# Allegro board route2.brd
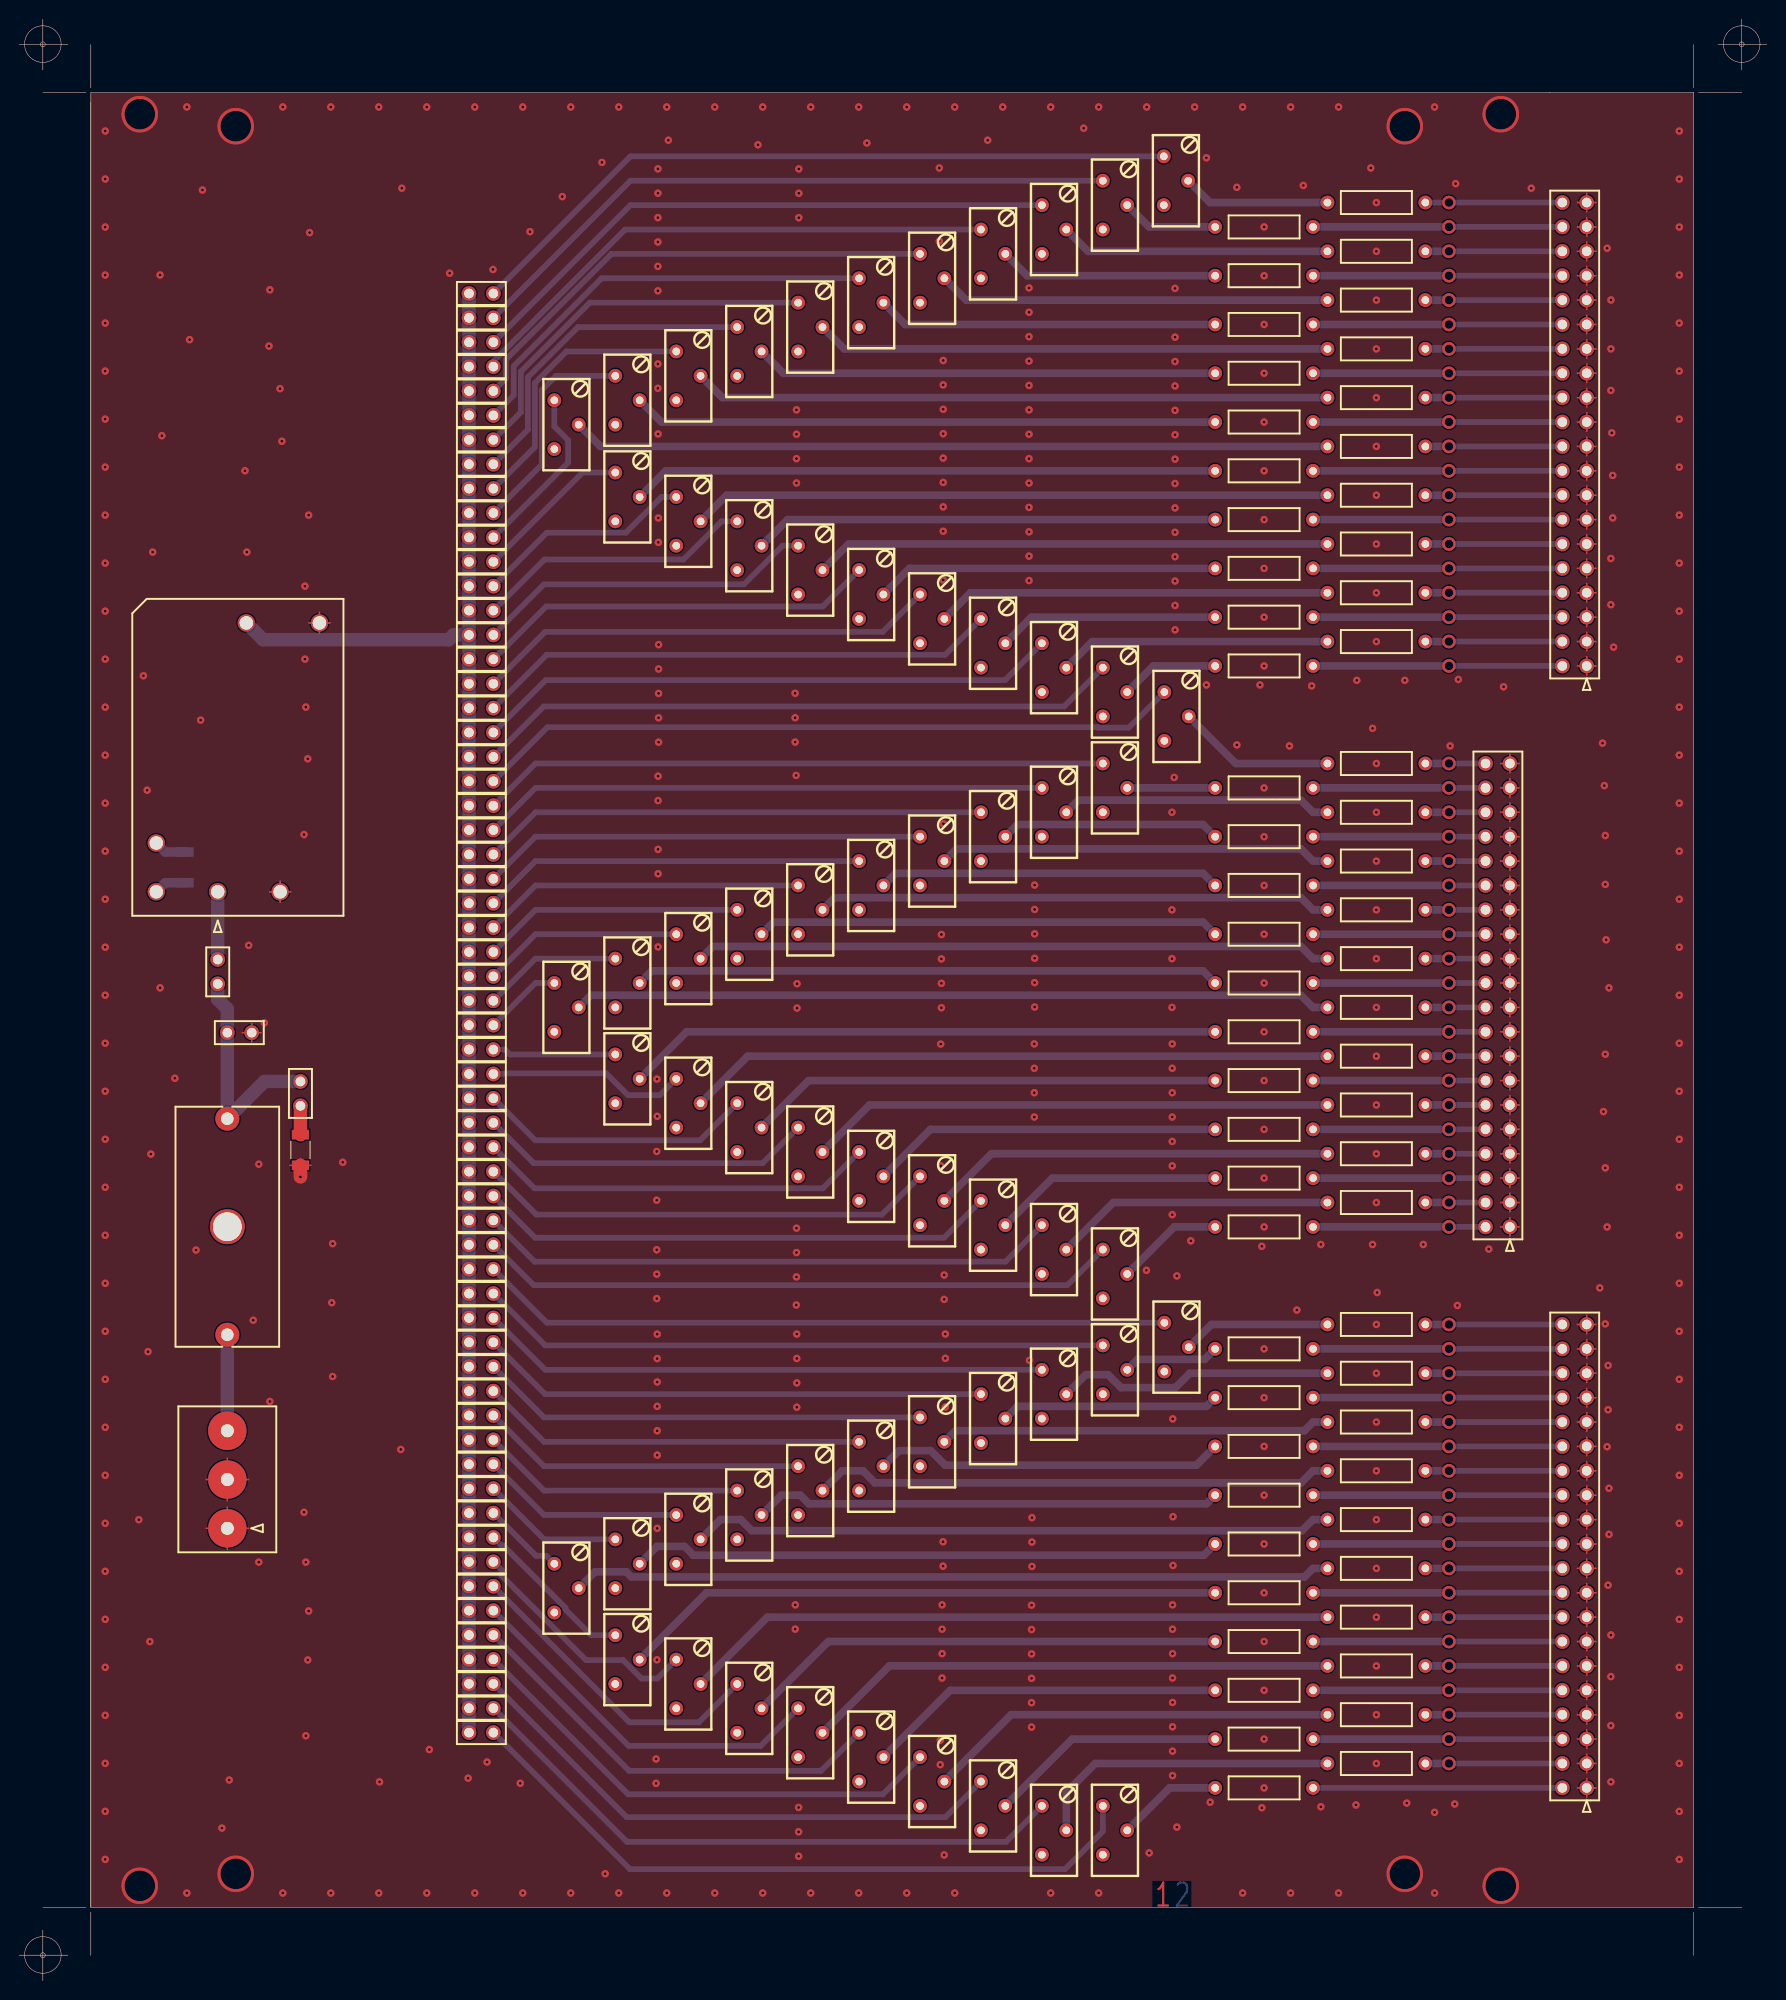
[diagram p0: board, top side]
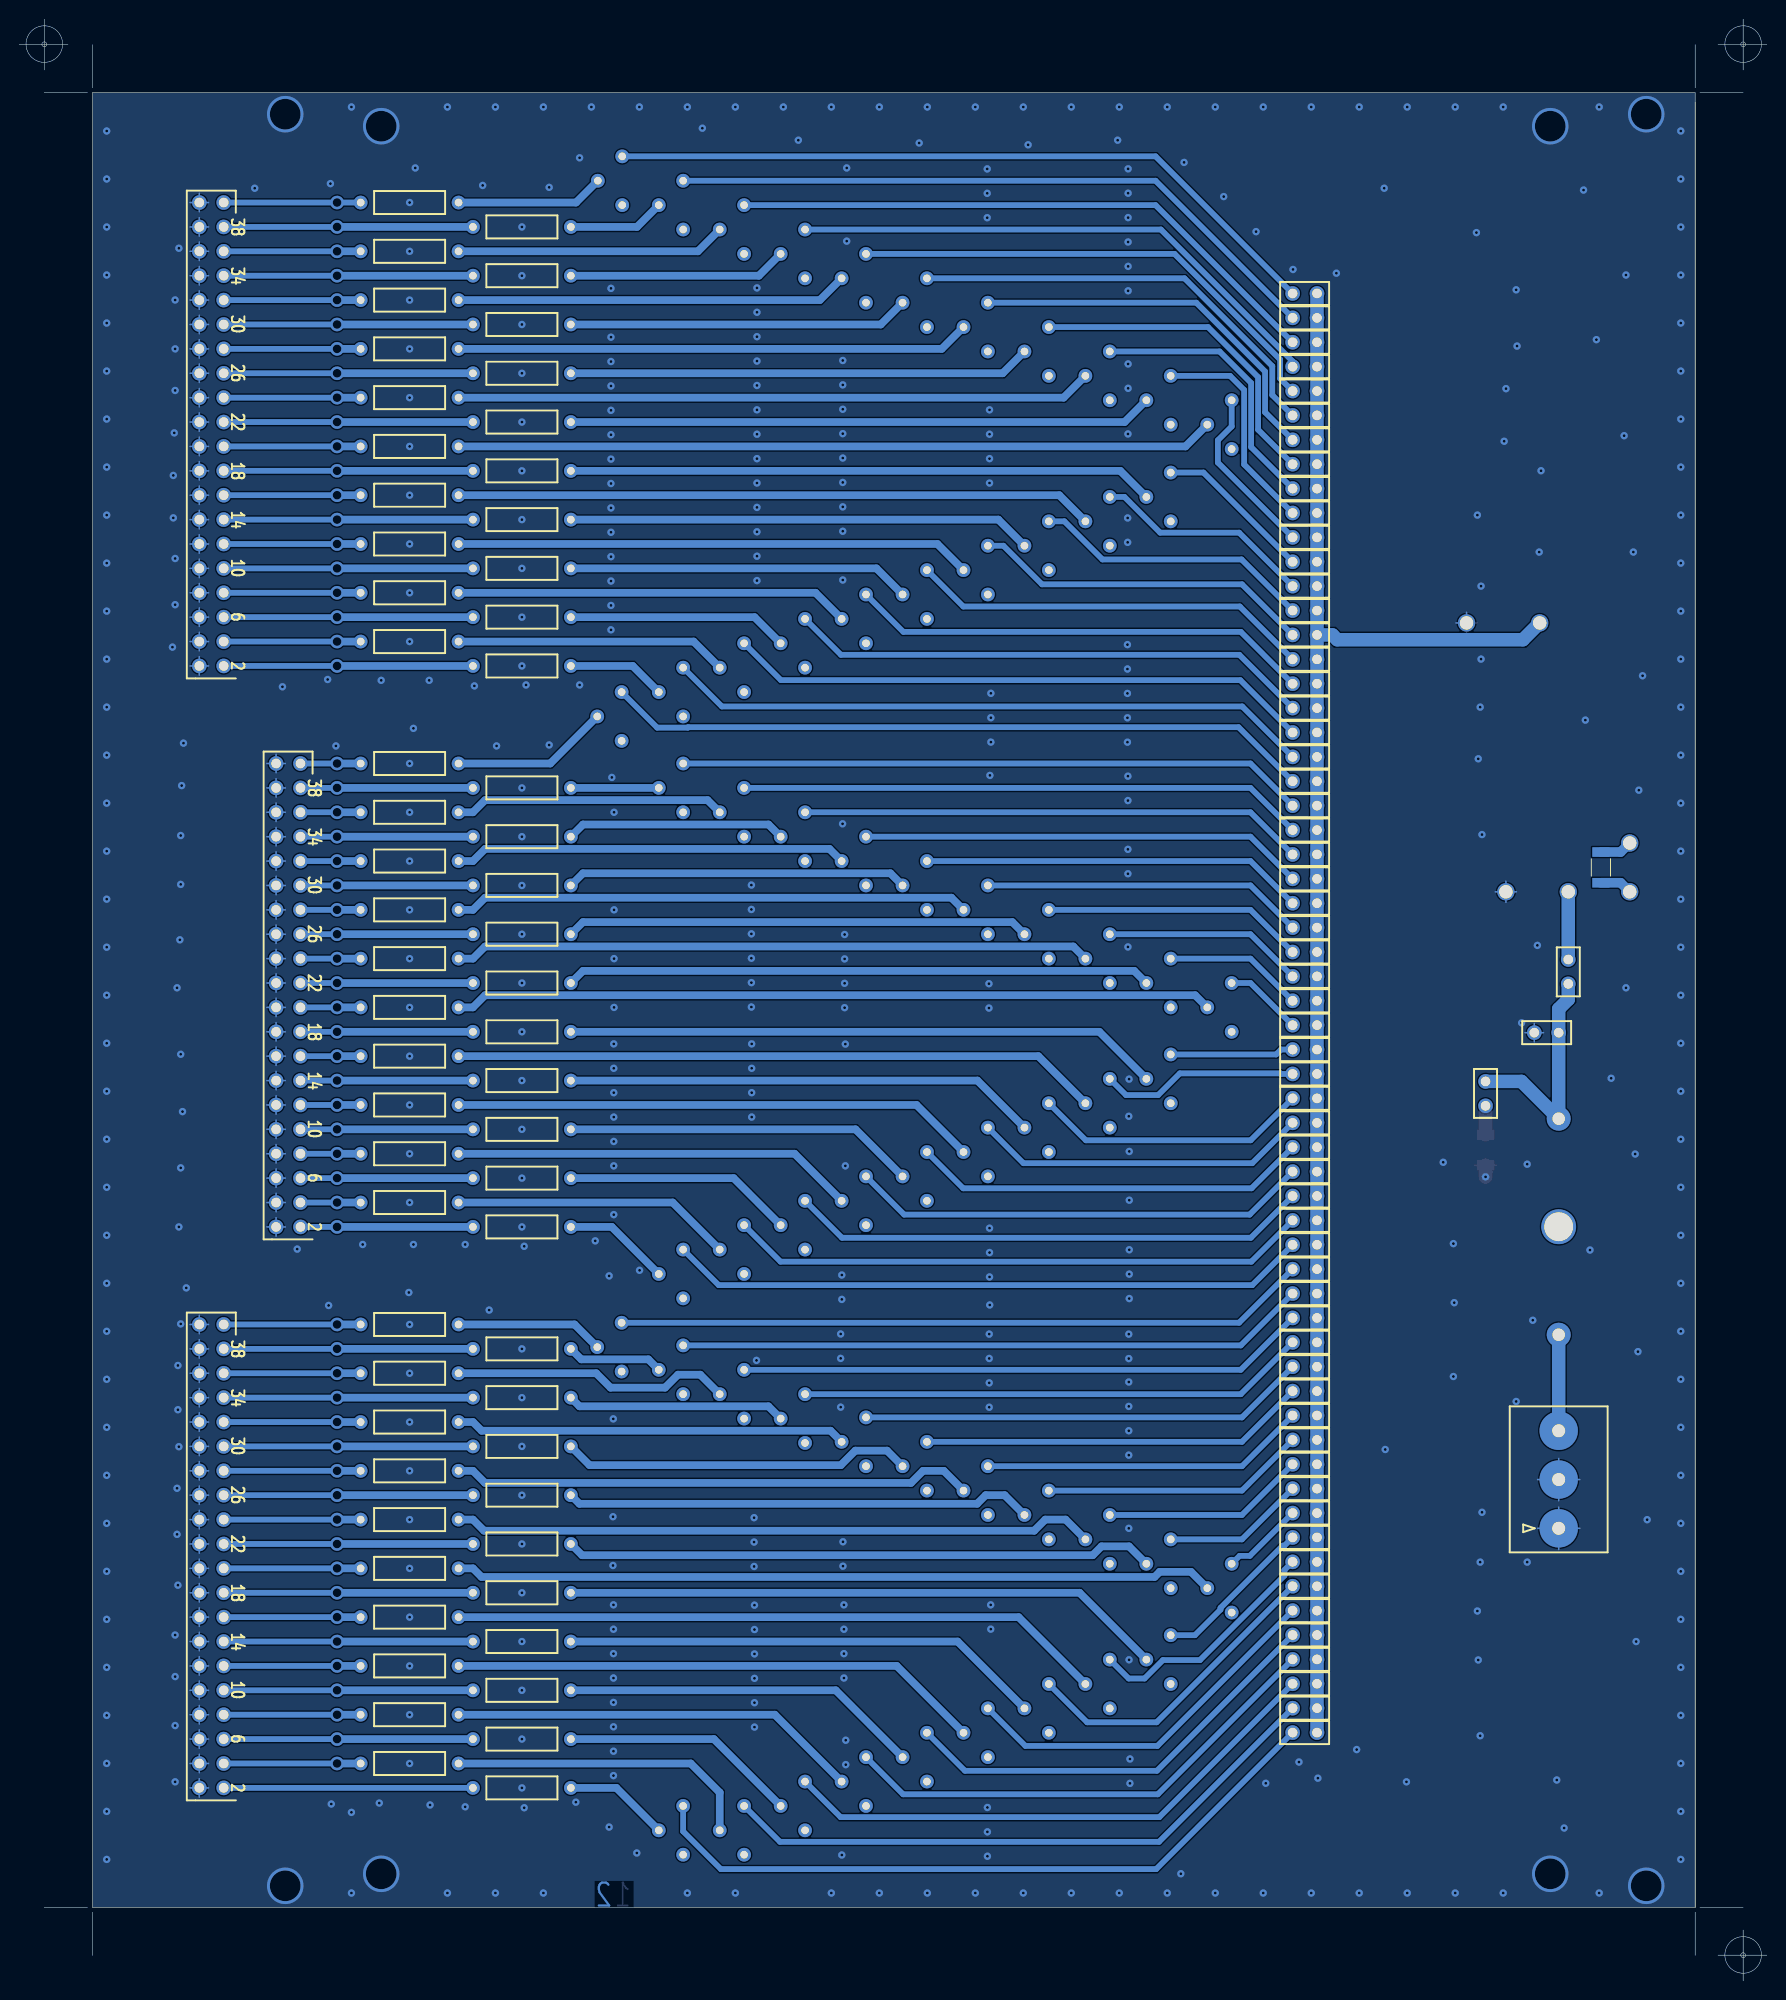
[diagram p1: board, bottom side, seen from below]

Outline 182.08 x 204.28 mm; copper layers: TOP, BOTTOM. Coordinates in mm from the lower left corner of the outline.
Outline path: 6.96,196.64 2.46,196.64 ; 6.96,7.64 2.46,7.64 ; 7.46,197.14 7.46,201.64 ; 7.46,7.64 7.46,196.64 174.46,196.64 174.46,7.64 7.46,7.64 ; 7.46,7.64 7.46,195.64 ; 7.46,7.14 7.46,2.64 ; 174.46,197.14 174.46,201.64 ; 174.46,7.14 174.46,2.64 ; 174.96,196.64 179.46,196.64 ; 174.96,7.64 179.46,7.64

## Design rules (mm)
constraint set DEFAULT: min track width 0.15, pair gap 0.15

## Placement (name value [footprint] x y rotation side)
B1  -  [BORNIER3B5080]  21.68 47.12 90 top
C1  47u  [S32X16_1206]  17.28 114.35 90 bottom
C2  100n  [S32X16_1206]  29.3 84.92 90 top
F1  10A  [FUSUP225X96]  21.68 67.28 90 top
J1  -  [CONHE13D2X20M]  163.31 136.93 0 top
J2  -  [CONHE13D2X20M]  155.31 78.51 0 top
J3  -  [CONHE13D2X20M]  163.31 20.09 0 top
NOREF  -  []  7.46 7.64 0 top
NOREF#2  -  []  2.46 2.64 0 top
NOREF#3  -  []  179.46 201.64 0 top
NOREF#4  -  []  2.46 201.64 0 top
NOREF#5  -  []  7.46 7.64 90 top
PO1  100  [POT_3296Y]  119.25 190 0 top
PO2  100  [POT_3296Y]  112.9 187.46 0 top
PO3  100  [POT_3296Y]  106.55 184.92 0 top
PO4  100  [POT_3296Y]  100.2 182.38 0 top
PO5  100  [POT_3296Y]  93.85 179.84 0 top
PO6  100  [POT_3296Y]  87.5 177.3 0 top
PO7  100  [POT_3296Y]  81.15 174.76 0 top
PO8  100  [POT_3296Y]  74.8 172.22 0 top
PO9  100  [POT_3296Y]  68.45 169.68 0 top
PO10  100  [POT_3296Y]  62.1 167.14 0 top
PO11  100  [POT_3296Y]  55.75 164.6 0 top
PO12  100  [POT_3296Y]  62.1 157.07 0 top
PO13  100  [POT_3296Y]  68.45 154.53 0 top
PO14  100  [POT_3296Y]  74.8 151.99 0 top
PO15  100  [POT_3296Y]  81.15 149.45 0 top
PO16  100  [POT_3296Y]  87.5 146.91 0 top
PO17  100  [POT_3296Y]  93.85 144.37 0 top
PO18  100  [POT_3296Y]  100.2 141.83 0 top
PO19  100  [POT_3296Y]  106.55 139.29 0 top
PO20  100  [POT_3296Y]  112.9 136.75 0 top
PO21  100  [POT_3296Y]  119.31 134.21 0 top
PO22  100  [POT_3296Y]  112.9 126.77 0 top
PO23  100  [POT_3296Y]  106.55 124.23 0 top
PO24  100  [POT_3296Y]  100.2 121.69 0 top
PO25  100  [POT_3296Y]  93.85 119.15 0 top
PO26  100  [POT_3296Y]  87.5 116.61 0 top
PO27  100  [POT_3296Y]  81.15 114.07 0 top
PO28  100  [POT_3296Y]  74.8 111.53 0 top
PO29  100  [POT_3296Y]  68.45 108.99 0 top
PO30  100  [POT_3296Y]  62.1 106.45 0 top
PO31  100  [POT_3296Y]  55.75 103.91 0 top
PO32  100  [POT_3296Y]  62.1 96.47 0 top
PO33  100  [POT_3296Y]  68.45 93.93 0 top
PO34  100  [POT_3296Y]  74.8 91.39 0 top
PO35  100  [POT_3296Y]  81.15 88.85 0 top
PO36  100  [POT_3296Y]  87.5 86.31 0 top
PO37  100  [POT_3296Y]  93.85 83.77 0 top
PO38  100  [POT_3296Y]  100.2 81.23 0 top
PO39  100  [POT_3296Y]  106.55 78.69 0 top
PO40  100  [POT_3296Y]  112.9 76.15 0 top
PO41  100  [POT_3296Y]  119.31 68.53 0 top
PO42  100  [POT_3296Y]  112.9 66.17 0 top
PO43  100  [POT_3296Y]  106.55 63.63 0 top
PO44  100  [POT_3296Y]  100.2 61.09 0 top
PO45  100  [POT_3296Y]  93.85 58.67 0 top
PO46  100  [POT_3296Y]  87.5 56.13 0 top
PO47  100  [POT_3296Y]  81.15 53.59 0 top
PO48  100  [POT_3296Y]  74.8 51.05 0 top
PO49  100  [POT_3296Y]  68.45 48.51 0 top
PO50  100  [POT_3296Y]  62.1 45.97 0 top
PO51  100  [POT_3296Y]  55.75 43.43 0 top
PO52  100  [POT_3296Y]  62.1 35.99 0 top
PO53  100  [POT_3296Y]  68.45 33.45 0 top
PO54  100  [POT_3296Y]  74.8 30.91 0 top
PO55  100  [POT_3296Y]  81.15 28.37 0 top
PO56  100  [POT_3296Y]  87.5 25.83 0 top
PO57  100  [POT_3296Y]  93.85 23.29 0 top
PO58  100  [POT_3296Y]  100.2 20.75 0 top
PO59  100  [POT_3296Y]  106.55 18.21 0 top
PO60  100  [POT_3296Y]  112.9 18.21 0 top
R1  100  [R100]  146.5 185.19 180 top
R2  100  [R100]  134.8 182.65 180 top
R3  100  [R100]  146.5 180.11 180 top
R4  100  [R100]  134.8 177.57 180 top
R5  100  [R100]  146.5 175.03 180 top
R6  100  [R100]  134.8 172.49 180 top
R7  100  [R100]  146.5 169.95 180 top
R8  100  [R100]  134.8 167.41 180 top
R9  100  [R100]  146.5 164.87 180 top
R10  100  [R100]  134.8 162.33 180 top
R11  100  [R100]  146.5 159.79 180 top
R12  100  [R100]  134.8 157.25 180 top
R13  100  [R100]  146.5 154.71 180 top
R14  100  [R100]  134.8 152.17 180 top
R15  100  [R100]  146.5 149.63 180 top
R16  100  [R100]  134.8 147.09 180 top
R17  100  [R100]  146.5 144.55 180 top
R18  100  [R100]  134.8 142.01 180 top
R19  100  [R100]  146.5 139.47 180 top
R20  100  [R100]  134.8 136.93 180 top
R21  100  [R100]  146.5 126.77 180 top
R22  100  [R100]  134.8 124.23 180 top
R23  100  [R100]  146.5 121.69 180 top
R24  100  [R100]  134.8 119.15 180 top
R25  100  [R100]  146.5 116.61 180 top
R26  100  [R100]  134.8 114.07 180 top
R27  100  [R100]  146.5 111.53 180 top
R28  100  [R100]  134.8 108.99 180 top
R29  100  [R100]  146.5 106.45 180 top
R30  100  [R100]  134.8 103.91 180 top
R31  100  [R100]  146.5 101.37 180 top
R32  100  [R100]  134.8 98.83 180 top
R33  100  [R100]  146.5 96.29 180 top
R34  100  [R100]  134.8 93.75 180 top
R35  100  [R100]  146.5 91.21 180 top
R36  100  [R100]  134.8 88.67 180 top
R37  100  [R100]  146.5 86.13 180 top
R38  100  [R100]  134.8 83.59 180 top
R39  100  [R100]  146.5 81.05 180 top
R40  100  [R100]  134.8 78.51 180 top
R41  100  [R100]  146.5 68.35 180 top
R42  100  [R100]  134.8 65.81 180 top
R43  100  [R100]  146.5 63.27 180 top
R44  100  [R100]  134.8 60.73 180 top
R45  100  [R100]  146.5 58.19 180 top
R46  100  [R100]  134.8 55.65 180 top
R47  100  [R100]  146.5 53.11 180 top
R48  100  [R100]  134.8 50.57 180 top
R49  100  [R100]  146.5 48.03 180 top
R50  100  [R100]  134.8 45.49 180 top
R51  100  [R100]  146.5 42.95 180 top
R52  100  [R100]  134.8 40.41 180 top
R53  100  [R100]  146.5 37.87 180 top
R54  100  [R100]  134.8 35.33 180 top
R55  100  [R100]  146.5 32.79 180 top
R56  100  [R100]  134.8 30.25 180 top
R57  100  [R100]  146.5 27.71 180 top
R58  100  [R100]  134.8 25.17 180 top
R59  100  [R100]  146.5 22.63 180 top
R60  100  [R100]  134.8 20.09 180 top
S1  -  [CONHE13D2M]  49.4 175.72 180 top
S2  -  [CONHE13D2M]  49.4 173.18 180 top
S3  -  [CONHE13D2M]  49.4 170.64 180 top
S4  -  [CONHE13D2M]  49.4 168.1 180 top
S5  -  [CONHE13D2M]  49.4 165.56 180 top
S6  -  [CONHE13D2M]  49.4 163.02 180 top
S7  -  [CONHE13D2M]  49.4 160.48 180 top
S8  -  [CONHE13D2M]  49.4 157.94 180 top
S9  -  [CONHE13D2M]  49.4 155.4 180 top
S10  -  [CONHE13D2M]  49.4 152.86 180 top
S11  -  [CONHE13D2M]  49.4 150.32 180 top
S12  -  [CONHE13D2M]  49.4 147.78 180 top
S13  -  [CONHE13D2M]  49.4 145.24 180 top
S14  -  [CONHE13D2M]  49.4 142.7 180 top
S15  -  [CONHE13D2M]  49.4 140.16 180 top
S16  -  [CONHE13D2M]  49.4 137.62 180 top
S17  -  [CONHE13D2M]  49.4 135.08 180 top
S18  -  [CONHE13D2M]  49.4 132.54 180 top
S19  -  [CONHE13D2M]  49.4 130 180 top
S20  -  [CONHE13D2M]  49.4 127.46 180 top
S21  -  [CONHE13D2M]  49.4 124.92 180 top
S22  -  [CONHE13D2M]  49.4 122.38 180 top
S23  -  [CONHE13D2M]  49.4 119.84 180 top
S24  -  [CONHE13D2M]  49.4 117.3 180 top
S25  -  [CONHE13D2M]  49.4 114.76 180 top
S26  -  [CONHE13D2M]  49.4 112.22 180 top
S27  -  [CONHE13D2M]  49.4 109.68 180 top
S28  -  [CONHE13D2M]  49.4 107.14 180 top
S29  -  [CONHE13D2M]  49.4 104.6 180 top
S30  -  [CONHE13D2M]  49.4 102.06 180 top
S31  -  [CONHE13D2M]  49.4 99.52 180 top
S32  -  [CONHE13D2M]  49.4 96.98 180 top
S33  -  [CONHE13D2M]  49.4 94.44 180 top
S34  -  [CONHE13D2M]  49.4 91.9 180 top
S35  -  [CONHE13D2M]  49.4 89.35 180 top
S36  -  [CONHE13D2M]  49.4 86.81 180 top
S37  -  [CONHE13D2M]  49.4 84.27 180 top
S38  -  [CONHE13D2M]  49.4 81.73 180 top
S39  -  [CONHE13D2M]  49.4 79.19 180 top
S40  -  [CONHE13D2M]  49.4 76.65 180 top
S41  -  [CONHE13D2M]  49.4 74.11 180 top
S42  -  [CONHE13D2M]  49.4 71.57 180 top
S43  -  [CONHE13D2M]  49.4 69.03 180 top
S44  -  [CONHE13D2M]  49.4 66.49 180 top
S45  -  [CONHE13D2M]  49.4 63.95 180 top
S46  -  [CONHE13D2M]  49.4 61.41 180 top
S47  -  [CONHE13D2M]  49.4 58.87 180 top
S48  -  [CONHE13D2M]  49.4 56.33 180 top
S49  -  [CONHE13D2M]  49.4 53.79 180 top
S50  -  [CONHE13D2M]  49.4 51.25 180 top
S51  -  [CONHE13D2M]  49.4 48.71 180 top
S52  -  [CONHE13D2M]  49.4 46.17 180 top
S53  -  [CONHE13D2M]  49.4 43.63 180 top
S54  -  [CONHE13D2M]  49.4 41.09 180 top
S55  -  [CONHE13D2M]  49.4 38.55 180 top
S56  -  [CONHE13D2M]  49.4 36.01 180 top
S57  -  [CONHE13D2M]  49.4 33.47 180 top
S58  -  [CONHE13D2M]  49.4 30.93 180 top
S59  -  [CONHE13D2M]  49.4 28.39 180 top
S60  -  [CONHE13D2M]  49.4 25.85 180 top
S61  -  [CONHE13D2M]  20.68 103.82 90 top
S62  -  [CONHE13D2M]  21.68 98.74 0 top
S63  -  [CONHE13D2M]  29.3 93.66 270 top
U1  -  [CONV_TUHS10]  20.68 113.41 90 top

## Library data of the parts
B1 = BORNIER3B: part number: BORNIER3B5080
C1 = CAPA: part number: CAPA-47U,C1206S6.3V20%
C2 = CAPA: part number: CAPA-100N,C1206S50V5%
F1 = FUSUP2P: part number: POLYFUSE-10A,W
J1-J3 = CON40P: part number: CON40P-HE13D
PO1-PO60 = POT: part number: POT-100,1/2W11T_D
R1-R60 = RGEN: part number: RGEN-100,M500MW5%
S1-S63 = STRAP: part number: STRAP-2X1
U1 = CONVAC_DC_TUHS10: part number: CONVAC_DC

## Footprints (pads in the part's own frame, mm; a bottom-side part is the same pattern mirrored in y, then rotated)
BORNIER3B5080
  round 4 hole 1.35: 1(0,0) 2(5.08,0) 3(10.16,0)
CONHE13D2M
  round 1.52 hole 1: 1(0,0) 2(2.54,0)
CONHE13D2X20M
  round 1.52 hole 1: 1(0,0) 2(-2.54,0) 3(0,2.54) 4(-2.54,2.54) 5(0,5.08) 6(-2.54,5.08) 7(0,7.62) 8(-2.54,7.62) 9(0,10.16) 10(-2.54,10.16) 11(0,12.7) 12(-2.54,12.7) 13(0,15.24) 14(-2.54,15.24) 15(0,17.78) 16(-2.54,17.78) 17(0,20.32) 18(-2.54,20.32) 19(0,22.86) 20(-2.54,22.86) 21(0,25.4) 22(-2.54,25.4) 23(0,27.94) 24(-2.54,27.94) 25(0,30.48) 26(-2.54,30.48) 27(0,33.02) 28(-2.54,33.02) 29(0,35.56) 30(-2.54,35.56) 31(0,38.1) 32(-2.54,38.1) 33(0,40.64) 34(-2.54,40.64) 35(0,43.18) 36(-2.54,43.18) 37(0,45.72) 38(-2.54,45.72) 39(0,48.26) 40(-2.54,48.26)
CONV_TUHS10
  round 1.8 hole 1.4: 1(0,0) 2(0,-6.5) 3(0,6.4) 4(5.08,6.4) 5(28,-2.98) 6(28,-10.6)
FUSUP225X96
  round 3.63 hole 3: (11.25,0)
  round 2.5 hole 1.3: 1(0,0) 2(22.5,0)
POT_3296Y
  round 1.43 hole 0.8: 1(0,0) 2(2.54,-2.54) 3(0,-5.08)
R100
  round 1.43 hole 0.8: 1(0,0) 2(10.2,0)
S32X16_1206
  rect 1x1.8 smd: 1(0,0) 2(3.2,0)

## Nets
GND: B1.1 B1.2 C2.1 J1.1 J1.3 J1.5 J1.7 J1.9 J1.11 J1.13 J1.15 J1.17 J1.19 J1.21 J1.23 J1.25 J1.27 J1.29 J1.31 J1.33 J1.35 J1.37 J1.39 J2.1 J2.3 J2.5 J2.7 J2.9 J2.11 J2.13 J2.15 J2.17 J2.19 J2.21 J2.23 J2.25 J2.27 J2.29 J2.31 J2.33 J2.35 J2.37 J2.39 J3.1 J3.3 J3.5 J3.7 J3.9 J3.11 J3.13 J3.15 J3.17 J3.19 J3.21 J3.23 J3.25 J3.27 J3.29 J3.31 J3.33 J3.35 J3.37 J3.39 S62.2(B) U1.2(AC2) U1.6
UNNAMED_1_BORNIER3B_I185_C: B1.3(C) F1.1
UNNAMED_1_CAPA_I190_B: C2.2(B<0>) S63.2(B)
UNNAMED_1_CAPA_I193_A: C1.1 U1.3
UNNAMED_1_CAPA_I193_B: C1.2(B<0>) U1.4
UNNAMED_1_CON40P_I1_A: J1.10(A<9>) R16.1
UNNAMED_1_CON40P_I1_A_1: J1.8 R17.1
UNNAMED_1_CON40P_I1_A_2: J1.6 R18.1
UNNAMED_1_CON40P_I1_A_3: J1.4 R19.1
UNNAMED_1_CON40P_I1_A_4: J1.40 R1.1
UNNAMED_1_CON40P_I1_A_5: J1.38 R2.1
UNNAMED_1_CON40P_I1_A_6: J1.36 R3.1
UNNAMED_1_CON40P_I1_A_7: J1.34 R4.1
UNNAMED_1_CON40P_I1_A_8: J1.32 R5.1
UNNAMED_1_CON40P_I1_A_9: J1.30 R6.1
UNNAMED_1_CON40P_I1_A_10: J1.28 R7.1
UNNAMED_1_CON40P_I1_A_11: J1.26 R8.1
UNNAMED_1_CON40P_I1_A_12: J1.24 R9.1
UNNAMED_1_CON40P_I1_A_13: J1.22 R10.1
UNNAMED_1_CON40P_I1_A_14: J1.2 R20.1
UNNAMED_1_CON40P_I1_A_15: J1.20 R11.1
UNNAMED_1_CON40P_I1_A_16: J1.18 R12.1
UNNAMED_1_CON40P_I1_A_17: J1.16 R13.1
UNNAMED_1_CON40P_I1_A_18: J1.14 R14.1
UNNAMED_1_CON40P_I1_A_19: J1.12 R15.1
UNNAMED_1_CON40P_I2_A: J3.28 R47.1
UNNAMED_1_CON40P_I2_A_1: J3.30 R46.1
UNNAMED_1_CON40P_I2_A_2: J3.38 R42.1
UNNAMED_1_CON40P_I2_A_3: J3.32 R45.1
UNNAMED_1_CON40P_I2_A_4: J3.34 R44.1
UNNAMED_1_CON40P_I2_A_5: J3.36 R43.1
UNNAMED_1_CON40P_I2_A_6: J3.40 R41.1
UNNAMED_1_CON40P_I2_A_7: J3.6 R58.1
UNNAMED_1_CON40P_I2_A_8: J3.8 R57.1
UNNAMED_1_CON40P_I2_A_9: J3.4 R59.1
UNNAMED_1_CON40P_I2_A_10: J3.2 R60.1
UNNAMED_1_CON40P_I2_A_11: J3.10(A<9>) R56.1
UNNAMED_1_CON40P_I2_A_12: J3.12 R55.1
UNNAMED_1_CON40P_I2_A_13: J3.14 R54.1
UNNAMED_1_CON40P_I2_A_14: J3.16 R53.1
UNNAMED_1_CON40P_I2_A_15: J3.18 R52.1
UNNAMED_1_CON40P_I2_A_16: J3.20 R51.1
UNNAMED_1_CON40P_I2_A_17: J3.22 R50.1
UNNAMED_1_CON40P_I2_A_18: J3.24 R49.1
UNNAMED_1_CON40P_I2_A_19: J3.26 R48.1
UNNAMED_1_CON40P_I3_A: J2.28 R27.1
UNNAMED_1_CON40P_I3_A_1: J2.30 R26.1
UNNAMED_1_CON40P_I3_A_2: J2.38 R22.1
UNNAMED_1_CON40P_I3_A_3: J2.32 R25.1
UNNAMED_1_CON40P_I3_A_4: J2.34 R24.1
UNNAMED_1_CON40P_I3_A_5: J2.36 R23.1
UNNAMED_1_CON40P_I3_A_6: J2.40 R21.1
UNNAMED_1_CON40P_I3_A_7: J2.6 R38.1
UNNAMED_1_CON40P_I3_A_8: J2.8 R37.1
UNNAMED_1_CON40P_I3_A_9: J2.4 R39.1
UNNAMED_1_CON40P_I3_A_10: J2.2 R40.1
UNNAMED_1_CON40P_I3_A_11: J2.10(A<9>) R36.1
UNNAMED_1_CON40P_I3_A_12: J2.12 R35.1
UNNAMED_1_CON40P_I3_A_13: J2.14 R34.1
UNNAMED_1_CON40P_I3_A_14: J2.16 R33.1
UNNAMED_1_CON40P_I3_A_15: J2.18 R32.1
UNNAMED_1_CON40P_I3_A_16: J2.20 R31.1
UNNAMED_1_CON40P_I3_A_17: J2.22 R30.1
UNNAMED_1_CON40P_I3_A_18: J2.24 R29.1
UNNAMED_1_CON40P_I3_A_19: J2.26 R28.1
UNNAMED_1_CONVACDCTUHS10_I194_A: S61.2(B) U1.1
UNNAMED_1_FUSUP2P_I186_B: F1.2(B) S61.1 S62.1 S63.1
UNNAMED_1_POT_I5_A: PO1.1 S1.1
UNNAMED_1_POT_I5_B: PO1.2 R1.2(B<0>)
UNNAMED_1_POT_I7_A: PO2.1 S2.1
UNNAMED_1_POT_I7_B: PO2.2 R2.2(B<0>)
UNNAMED_1_POT_I26_A: PO3.1 S3.1
UNNAMED_1_POT_I26_B: PO3.2 R3.2(B<0>)
UNNAMED_1_POT_I27_A: PO4.1 S4.1
UNNAMED_1_POT_I27_B: PO4.2 R4.2(B<0>)
UNNAMED_1_POT_I28_A: PO5.1 S5.1
UNNAMED_1_POT_I28_B: PO5.2 R5.2(B<0>)
UNNAMED_1_POT_I29_A: PO6.1 S6.1
UNNAMED_1_POT_I29_B: PO6.2 R6.2(B<0>)
UNNAMED_1_POT_I30_A: PO7.1 S7.1
UNNAMED_1_POT_I30_B: PO7.2 R7.2(B<0>)
UNNAMED_1_POT_I31_A: PO8.1 S8.1
UNNAMED_1_POT_I31_B: PO8.2 R8.2(B<0>)
UNNAMED_1_POT_I32_A: PO9.1 S9.1
UNNAMED_1_POT_I32_B: PO9.2 R9.2(B<0>)
UNNAMED_1_POT_I33_A: PO10.1 S10.1
UNNAMED_1_POT_I33_B: PO10.2 R10.2(B<0>)
UNNAMED_1_POT_I34_A: PO11.1 S11.1
UNNAMED_1_POT_I34_B: PO11.2 R11.2(B<0>)
UNNAMED_1_POT_I35_A: PO12.1 S12.1
UNNAMED_1_POT_I35_B: PO12.2 R12.2(B<0>)
UNNAMED_1_POT_I36_A: PO13.1 S13.1
UNNAMED_1_POT_I36_B: PO13.2 R13.2(B<0>)
UNNAMED_1_POT_I37_A: PO14.1 S14.1
UNNAMED_1_POT_I37_B: PO14.2 R14.2(B<0>)
UNNAMED_1_POT_I38_A: PO15.1 S15.1
UNNAMED_1_POT_I38_B: PO15.2 R15.2(B<0>)
UNNAMED_1_POT_I39_A: PO16.1 S16.1
UNNAMED_1_POT_I39_B: PO16.2 R16.2(B<0>)
UNNAMED_1_POT_I40_A: PO17.1 S17.1
UNNAMED_1_POT_I40_B: PO17.2 R17.2(B<0>)
UNNAMED_1_POT_I41_A: PO18.1 S18.1
UNNAMED_1_POT_I41_B: PO18.2 R18.2(B<0>)
UNNAMED_1_POT_I42_A: PO19.1 S19.1
UNNAMED_1_POT_I42_B: PO19.2 R19.2(B<0>)
UNNAMED_1_POT_I43_A: PO20.1 S20.1
UNNAMED_1_POT_I43_B: PO20.2 R20.2(B<0>)
UNNAMED_1_POT_I44_A: PO40.1 S40.1
UNNAMED_1_POT_I44_B: PO40.2 R40.2(B<0>)
UNNAMED_1_POT_I45_A: PO39.1 S39.1
UNNAMED_1_POT_I45_B: PO39.2 R39.2(B<0>)
UNNAMED_1_POT_I46_A: PO38.1 S38.1
UNNAMED_1_POT_I46_B: PO38.2 R38.2(B<0>)
UNNAMED_1_POT_I47_A: PO33.1 S33.1
UNNAMED_1_POT_I47_B: PO33.2 R33.2(B<0>)
UNNAMED_1_POT_I48_A: PO32.1 S32.1
UNNAMED_1_POT_I48_B: PO32.2 R32.2(B<0>)
UNNAMED_1_POT_I49_A: PO31.1 S31.1
UNNAMED_1_POT_I49_B: PO31.2 R31.2(B<0>)
UNNAMED_1_POT_I50_A: PO30.1 S30.1
UNNAMED_1_POT_I50_B: PO30.2 R30.2(B<0>)
UNNAMED_1_POT_I51_A: PO29.1 S29.1
UNNAMED_1_POT_I51_B: PO29.2 R29.2(B<0>)
UNNAMED_1_POT_I52_A: PO27.1 S27.1
UNNAMED_1_POT_I52_B: PO27.2 R27.2(B<0>)
UNNAMED_1_POT_I53_A: PO28.1 S28.1
UNNAMED_1_POT_I53_B: PO28.2 R28.2(B<0>)
UNNAMED_1_POT_I54_A: PO26.1 S26.1
UNNAMED_1_POT_I54_B: PO26.2 R26.2(B<0>)
UNNAMED_1_POT_I55_A: PO25.1 S25.1
UNNAMED_1_POT_I55_B: PO25.2 R25.2(B<0>)
UNNAMED_1_POT_I56_A: PO24.1 S24.1
UNNAMED_1_POT_I56_B: PO24.2 R24.2(B<0>)
UNNAMED_1_POT_I57_A: PO22.1 S22.1
UNNAMED_1_POT_I57_B: PO22.2 R22.2(B<0>)
UNNAMED_1_POT_I58_A: PO21.1 S21.1
UNNAMED_1_POT_I58_B: PO21.2 R21.2(B<0>)
UNNAMED_1_POT_I59_A: PO23.1 S23.1
UNNAMED_1_POT_I59_B: PO23.2 R23.2(B<0>)
UNNAMED_1_POT_I72_A: PO37.1 S37.1
UNNAMED_1_POT_I72_B: PO37.2 R37.2(B<0>)
UNNAMED_1_POT_I73_A: PO36.1 S36.1
UNNAMED_1_POT_I73_B: PO36.2 R36.2(B<0>)
UNNAMED_1_POT_I74_A: PO35.1 S35.1
UNNAMED_1_POT_I74_B: PO35.2 R35.2(B<0>)
UNNAMED_1_POT_I75_A: PO34.1 S34.1
UNNAMED_1_POT_I75_B: PO34.2 R34.2(B<0>)
UNNAMED_1_POT_I84_A: PO60.1 S60.1
UNNAMED_1_POT_I84_B: PO60.2 R60.2(B<0>)
UNNAMED_1_POT_I85_A: PO59.1 S59.1
UNNAMED_1_POT_I85_B: PO59.2 R59.2(B<0>)
UNNAMED_1_POT_I86_A: PO58.1 S58.1
UNNAMED_1_POT_I86_B: PO58.2 R58.2(B<0>)
UNNAMED_1_POT_I87_A: PO53.1 S53.1
UNNAMED_1_POT_I87_B: PO53.2 R53.2(B<0>)
UNNAMED_1_POT_I88_A: PO52.1 S52.1
UNNAMED_1_POT_I88_B: PO52.2 R52.2(B<0>)
UNNAMED_1_POT_I89_A: PO51.1 S51.1
UNNAMED_1_POT_I89_B: PO51.2 R51.2(B<0>)
UNNAMED_1_POT_I90_A: PO50.1 S50.1
UNNAMED_1_POT_I90_B: PO50.2 R50.2(B<0>)
UNNAMED_1_POT_I91_A: PO49.1 S49.1
UNNAMED_1_POT_I91_B: PO49.2 R49.2(B<0>)
UNNAMED_1_POT_I92_A: PO47.1 S47.1
UNNAMED_1_POT_I92_B: PO47.2 R47.2(B<0>)
UNNAMED_1_POT_I93_A: PO48.1 S48.1
UNNAMED_1_POT_I93_B: PO48.2 R48.2(B<0>)
UNNAMED_1_POT_I94_A: PO46.1 S46.1
UNNAMED_1_POT_I94_B: PO46.2 R46.2(B<0>)
UNNAMED_1_POT_I95_A: PO45.1 S45.1
UNNAMED_1_POT_I95_B: PO45.2 R45.2(B<0>)
UNNAMED_1_POT_I96_A: PO44.1 S44.1
UNNAMED_1_POT_I96_B: PO44.2 R44.2(B<0>)
UNNAMED_1_POT_I97_A: PO42.1 S42.1
UNNAMED_1_POT_I97_B: PO42.2 R42.2(B<0>)
UNNAMED_1_POT_I98_A: PO41.1 S41.1
UNNAMED_1_POT_I98_B: PO41.2 R41.2(B<0>)
UNNAMED_1_POT_I99_A: PO43.1 S43.1
UNNAMED_1_POT_I99_B: PO43.2 R43.2(B<0>)
UNNAMED_1_POT_I112_A: PO57.1 S57.1
UNNAMED_1_POT_I112_B: PO57.2 R57.2(B<0>)
UNNAMED_1_POT_I113_A: PO56.1 S56.1
UNNAMED_1_POT_I113_B: PO56.2 R56.2(B<0>)
UNNAMED_1_POT_I114_A: PO55.1 S55.1
UNNAMED_1_POT_I114_B: PO55.2 R55.2(B<0>)
UNNAMED_1_POT_I115_A: PO54.1 S54.1
UNNAMED_1_POT_I115_B: PO54.2 R54.2(B<0>)
UNNAMED_1_STRAP_I125_B: S1.2(B) S2.2(B) S3.2(B) S4.2(B) S5.2(B) S6.2(B) S7.2(B) S8.2(B) S9.2(B) S10.2(B) S11.2(B) S12.2(B) S13.2(B) S14.2(B) S15.2(B) S16.2(B) S17.2(B) S18.2(B) S19.2(B) S20.2(B) S21.2(B) S22.2(B) S23.2(B) S24.2(B) S25.2(B) S26.2(B) S27.2(B) S28.2(B) S29.2(B) S30.2(B) S31.2(B) S32.2(B) S33.2(B) S34.2(B) S35.2(B) S36.2(B) S37.2(B) S38.2(B) S39.2(B) S40.2(B) S41.2(B) S42.2(B) S43.2(B) S44.2(B) S45.2(B) S46.2(B) S47.2(B) S48.2(B) S49.2(B) S50.2(B) S51.2(B) S52.2(B) S53.2(B) S54.2(B) S55.2(B) S56.2(B) S57.2(B) S58.2(B) S59.2(B) S60.2(B) U1.5

Pads without a net: PO1 3; PO2 3; PO3 3; PO4 3; PO5 3; PO6 3; PO7 3; PO8 3; PO9 3; PO10 3; PO11 3; PO12 3; PO13 3; PO14 3; PO15 3; PO16 3; PO17 3; PO18 3; PO19 3; PO20 3; PO21 3; PO22 3; PO23 3; PO24 3; PO25 3; PO26 3; PO27 3; PO28 3; PO29 3; PO30 3; PO31 3; PO32 3; PO33 3; PO34 3; PO35 3; PO36 3; PO37 3; PO38 3; PO39 3; PO40 3; PO41 3; PO42 3; PO43 3; PO44 3; PO45 3; PO46 3; PO47 3; PO48 3; PO49 3; PO50 3; PO51 3; PO52 3; PO53 3; PO54 3; PO55 3; PO56 3; PO57 3; PO58 3; PO59 3; PO60 3

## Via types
v1: diameter 1.42, hole 0.9, TOP to BOTTOM, 59 vias
v2: diameter 0.77, hole 0.3, TOP to BOTTOM, 480 vias
v3: diameter 3.8, hole 3.2, TOP to BOTTOM, 8 vias

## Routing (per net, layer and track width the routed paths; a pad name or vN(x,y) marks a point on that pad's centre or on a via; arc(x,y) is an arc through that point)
GND: length 524.3
  TOP w0.15: 163.31,143.59 J1.7 ; J1.7 164.27,144.55 ; J1.7 162.35,144.55 ; J1.7 163.31,145.51 ; J3.11 164.27,32.79 ; J3.11 162.35,32.79 ; J3.11 163.31,33.75 ; J3.11 163.31,31.83 ; 26.08,113.41 U1.2 ; U1.2 27.18,112.31 ; U1.2 28.28,113.41 ; U1.2 27.18,114.51 ; 162.35,167.41 J1.25 ; J1.25 163.31,168.37 ; J1.25 164.27,167.41 ; J1.25 163.31,166.45 ; J3.37 163.31,66.77 ; J3.37 163.31,64.85 ; J3.37 162.35,65.81 ; J3.37 164.27,65.81 ; 155.31,92.79 J2.13 ; J2.13 156.27,93.75 ; J2.13 155.31,94.71 ; J2.13 154.35,93.75 ; J1.39 164.27,185.19 ; J1.39 162.35,185.19 ; J1.39 163.31,184.23 ; J1.39 163.31,186.15 ; J2.21 155.31,104.87 ; J2.21 156.27,103.91 ; J2.21 154.35,103.91 ; J2.21 155.31,102.95 ; J3.21 163.31,46.45 ; J3.21 162.35,45.49 ; J3.21 164.27,45.49 ; J3.21 163.31,44.53 ; 31.28,140.31 U1.6 ; U1.6 31.28,142.51 ; U1.6 32.38,141.41 ; U1.6 30.18,141.41 ; 23.26,98.74 S62.2 ; S62.2 25.18,98.74 ; S62.2 24.22,99.7 ; S62.2 24.22,97.78 ; J1.3 163.31,140.43 ; J1.3 162.35,139.47 ; J1.3 163.31,138.51 ; J1.3 164.27,139.47 ; 162.35,30.25 J3.9 ; J3.9 164.27,30.25 ; J3.9 163.31,31.21 ; J3.9 163.31,29.29 ; 162.35,40.41 J3.17 ; J3.17 163.31,39.45 ; J3.17 163.31,41.37 ; J3.17 164.27,40.41 ; 162.35,149.63 J1.11 ; J1.11 163.31,148.67 ; J1.11 163.31,150.59 ; J1.11 164.27,149.63 ; J3.13 164.27,35.33 ; J3.13 162.35,35.33 ; J3.13 163.31,34.37 ; J3.13 163.31,36.29 ; 162.35,182.65 J1.37 ; J1.37 163.31,181.69 ; J1.37 163.31,183.61 ; J1.37 164.27,182.65 ; 154.35,81.05 J2.3 ; J2.3 155.31,82.01 ; J2.3 156.27,81.05 ; J2.3 155.31,80.09 ; J1.29 163.31,173.45 ; J1.29 164.27,172.49 ; J1.29 163.31,171.53 ; J1.29 162.35,172.49 ; 163.31,24.21 J3.5 ; J3.5 163.31,26.13 ; J3.5 164.27,25.17 ; J3.5 162.35,25.17 ; J2.11 156.27,91.21 ; J2.11 155.31,90.25 ; J2.11 154.35,91.21 ; J2.11 155.31,92.17 ; J3.1 163.31,21.05 ; J3.1 163.31,19.13 ; J3.1 162.35,20.09 ; J3.1 164.27,20.09 ; J2.31 156.27,116.61 ; J2.31 155.31,117.57 ; J2.31 154.35,116.61 ; J2.31 155.31,115.65 ; J2.37 156.27,124.23 ; J2.37 155.31,123.27 ; J2.37 154.35,124.23 ; J2.37 155.31,125.19 ; J2.5 156.27,83.59 ; J2.5 154.35,83.59 ; J2.5 155.31,84.55 ; J2.5 155.31,82.63 ; J3.15 163.31,38.83 ; J3.15 164.27,37.87 ; J3.15 163.31,36.91 ; J3.15 162.35,37.87 ; 162.35,169.95 J1.27 ; J1.27 163.31,168.99 ; J1.27 164.27,169.95 ; J1.27 163.31,170.91 ; 163.31,49.61 J3.25 ; J3.25 164.27,50.57 ; J3.25 162.35,50.57 ; J3.25 163.31,51.53 ; J3.19 163.31,43.91 ; J3.19 163.31,41.99 ; J3.19 164.27,42.95 ; J3.19 162.35,42.95 ; J3.39 164.27,68.35 ; J3.39 163.31,67.39 ; J3.39 162.35,68.35 ; J3.39 163.31,69.31 ; J1.9 164.27,147.09 ; J1.9 163.31,148.05 ; J1.9 163.31,146.13 ; J1.9 162.35,147.09 ; 155.31,120.73 J2.35 ; J2.35 155.31,122.65 ; J2.35 154.35,121.69 ; J2.35 156.27,121.69 ; B1.1 21.68,49.32 ; B1.1 23.88,47.12 ; B1.1 21.68,44.92 ; B1.1 19.48,47.12 ; 19.48,52.2 B1.2 ; B1.2 23.88,52.2 ; B1.2 21.68,50 ; B1.2 21.68,54.4 ; 162.35,27.71 J3.7 ; J3.7 163.31,26.75 ; J3.7 163.31,28.67 ; J3.7 164.27,27.71 ; 155.31,87.71 J2.9 ; J2.9 155.31,89.63 ; J2.9 154.35,88.67 ; J2.9 156.27,88.67 ; J1.35 164.27,180.11 ; J1.35 163.31,181.07 ; J1.35 163.31,179.15 ; J1.35 162.35,180.11 ; 162.35,142.01 J1.5 ; J1.5 163.31,142.97 ; J1.5 163.31,141.05 ; J1.5 164.27,142.01 ; J3.31 164.27,58.19 ; J3.31 162.35,58.19 ; J3.31 163.31,59.15 ; J3.31 163.31,57.23 ; 163.31,174.07 J1.31 ; J1.31 163.31,175.99 ; J1.31 162.35,175.03 ; J1.31 164.27,175.03 ; J1.17 164.27,157.25 ; J1.17 162.35,157.25 ; J1.17 163.31,158.21 ; J1.17 163.31,156.29 ; 163.31,47.07 J3.23 ; J3.23 164.27,48.03 ; J3.23 163.31,48.99 ; J3.23 162.35,48.03 ; J2.25 155.31,109.95 ; J2.25 155.31,108.03 ; J2.25 154.35,108.99 ; J2.25 156.27,108.99 ; 162.35,63.27 J3.35 ; J3.35 163.31,62.31 ; J3.35 164.27,63.27 ; J3.35 163.31,64.23 ; J2.17 156.27,98.83 ; J2.17 154.35,98.83 ; J2.17 155.31,97.87 ; J2.17 155.31,99.79 ; J1.13 164.27,152.17 ; J1.13 162.35,152.17 ; J1.13 163.31,151.21 ; J1.13 163.31,153.13 ; 163.31,153.75 J1.15 ; J1.15 163.31,155.67 ; J1.15 164.27,154.71 ; J1.15 162.35,154.71 ; J3.29 164.27,55.65 ; J3.29 163.31,56.61 ; J3.29 163.31,54.69 ; J3.29 162.35,55.65 ; C2.1 30.4,84.92 ; C2.1 29.3,85.62 ; C2.1 28.2,84.92 ; 162.35,162.33 J1.21 ; J1.21 163.31,161.37 ; J1.21 164.27,162.33 ; J1.21 163.31,163.29 ; J2.19 156.27,101.37 ; J2.19 155.31,100.41 ; J2.19 154.35,101.37 ; J2.19 155.31,102.33 ; 163.31,21.67 J3.3 ; J3.3 163.31,23.59 ; J3.3 164.27,22.63 ; J3.3 162.35,22.63 ; 162.35,60.73 J3.33 ; J3.33 163.31,59.77 ; J3.33 163.31,61.69 ; J3.33 164.27,60.73 ; J2.39 156.27,126.77 ; J2.39 155.31,127.73 ; J2.39 154.35,126.77 ; J2.39 155.31,125.81 ; 162.35,159.79 J1.19 ; J1.19 163.31,160.75 ; J1.19 164.27,159.79 ; J1.19 163.31,158.83 ; J1.33 163.31,178.53 ; J1.33 162.35,177.57 ; J1.33 164.27,177.57 ; J1.33 163.31,176.61 ; 163.31,52.15 J3.27 ; J3.27 163.31,54.07 ; J3.27 164.27,53.11 ; J3.27 162.35,53.11 ; J2.15 155.31,97.25 ; J2.15 156.27,96.29 ; J2.15 154.35,96.29 ; J2.15 155.31,95.33 ; 155.31,77.55 J2.1 ; J2.1 155.31,79.47 ; J2.1 156.27,78.51 ; J2.1 154.35,78.51 ; 154.35,106.45 J2.23 ; J2.23 156.27,106.45 ; J2.23 155.31,107.41 ; J2.23 155.31,105.49 ; 155.31,118.19 J2.33 ; J2.33 156.27,119.15 ; J2.33 155.31,120.11 ; J2.33 154.35,119.15 ; 163.31,135.97 J1.1 ; J1.1 163.31,137.89 ; J1.1 162.35,136.93 ; J1.1 164.27,136.93 ; 163.31,163.91 J1.23 ; J1.23 164.27,164.87 ; J1.23 163.31,165.83 ; J1.23 162.35,164.87 ; J2.27 155.31,112.49 ; J2.27 154.35,111.53 ; J2.27 156.27,111.53 ; J2.27 155.31,110.57 ; J2.7 155.31,87.09 ; J2.7 156.27,86.13 ; J2.7 155.31,85.17 ; J2.7 154.35,86.13 ; 154.35,114.07 J2.29 ; J2.29 155.31,113.11 ; J2.29 156.27,114.07 ; J2.29 155.31,115.03
  TOP w1.4: C2.1 v2(29.3,83.72)
  BOTTOM w0.15: U1.6 31.28,142.51 ; U1.6 30.66,141.41 ; U1.6 32.38,141.41 ; J1.25 164.27,167.41 ; J1.25 163.31,166.45 ; J1.25 162.35,167.41 ; J1.25 163.31,168.37 ; 163.31,29.29 J3.9 ; J3.9 163.31,31.21 ; J3.9 164.27,30.25 ; J3.9 162.35,30.25 ; J2.27 155.31,112.49 ; J2.27 155.31,110.57 ; J2.27 154.35,111.53 ; J2.27 156.27,111.53 ; J3.37 164.27,65.81 ; J3.37 162.35,65.81 ; J3.37 163.31,64.85 ; J3.37 163.31,66.77 ; J2.29 156.27,114.07 ; J2.29 155.31,115.03 ; J2.29 155.31,113.11 ; J2.29 154.35,114.07 ; 154.35,86.13 J2.7 ; J2.7 156.27,86.13 ; J2.7 155.31,85.17 ; J2.7 155.31,87.09 ; J3.17 163.31,41.37 ; J3.17 162.35,40.41 ; J3.17 163.31,39.45 ; J3.17 164.27,40.41 ; J3.23 163.31,48.99 ; J3.23 163.31,47.07 ; J3.23 164.27,48.03 ; J3.23 162.35,48.03 ; J1.33 164.27,177.57 ; J1.33 163.31,176.61 ; J1.33 163.31,178.53 ; J1.33 162.35,177.57 ; J3.11 164.27,32.79 ; J3.11 163.31,33.75 ; J3.11 162.35,32.79 ; J3.11 163.31,31.83 ; 155.31,102.95 J2.21 ; J2.21 156.27,103.91 ; J2.21 155.31,104.87 ; J2.21 154.35,103.91 ; 162.35,136.93 J1.1 ; J1.1 163.31,135.97 ; J1.1 164.27,136.93 ; J1.1 163.31,137.89 ; 163.31,146.13 J1.9 ; J1.9 162.35,147.09 ; J1.9 163.31,148.05 ; J1.9 164.27,147.09 ; J2.23 156.27,106.45 ; J2.23 154.35,106.45 ; J2.23 155.31,105.49 ; J2.23 155.31,107.41 ; J3.35 163.31,64.23 ; J3.35 163.31,62.31 ; J3.35 162.35,63.27 ; J3.35 164.27,63.27 ; J3.27 164.27,53.11 ; J3.27 162.35,53.11 ; J3.27 163.31,54.07 ; J3.27 163.31,52.15 ; J1.23 163.31,165.83 ; J1.23 162.35,164.87 ; J1.23 164.27,164.87 ; J1.23 163.31,163.91 ; J3.15 163.31,38.83 ; J3.15 164.27,37.87 ; J3.15 162.35,37.87 ; J3.15 163.31,36.91 ; 23.26,98.74 S62.2 ; S62.2 24.22,99.7 ; S62.2 25.18,98.74 ; S62.2 24.22,97.78 ; J3.29 163.31,56.61 ; J3.29 162.35,55.65 ; J3.29 163.31,54.69 ; J3.29 164.27,55.65 ; J1.37 164.27,182.65 ; J1.37 162.35,182.65 ; J1.37 163.31,181.69 ; J1.37 163.31,183.61 ; 162.35,152.17 J1.13 ; J1.13 164.27,152.17 ; J1.13 163.31,153.13 ; J1.13 163.31,151.21 ; 154.35,116.61 J2.31 ; J2.31 155.31,117.57 ; J2.31 156.27,116.61 ; J2.31 155.31,115.65 ; 162.35,144.55 J1.7 ; J1.7 163.31,145.51 ; J1.7 164.27,144.55 ; J1.7 163.31,143.59 ; J1.29 164.27,172.49 ; J1.29 163.31,171.53 ; J1.29 163.31,173.45 ; J1.29 162.35,172.49 ; 154.35,124.23 J2.37 ; J2.37 156.27,124.23 ; J2.37 155.31,123.27 ; J2.37 155.31,125.19 ; 162.35,162.33 J1.21 ; J1.21 163.31,163.29 ; J1.21 163.31,161.37 ; J1.21 164.27,162.33 ; 162.35,185.19 J1.39 ; J1.39 163.31,186.15 ; J1.39 164.27,185.19 ; J1.39 163.31,184.23 ; J1.19 163.31,160.75 ; J1.19 163.31,158.83 ; J1.19 162.35,159.79 ; J1.19 164.27,159.79 ; J3.33 164.27,60.73 ; J3.33 163.31,59.77 ; J3.33 163.31,61.69 ; J3.33 162.35,60.73 ; 155.31,87.71 J2.9 ; J2.9 156.27,88.67 ; J2.9 155.31,89.63 ; J2.9 154.35,88.67 ; J2.11 155.31,92.17 ; J2.11 156.27,91.21 ; J2.11 155.31,90.25 ; J2.11 154.35,91.21 ; J3.7 164.27,27.71 ; J3.7 163.31,28.67 ; J3.7 163.31,26.75 ; J3.7 162.35,27.71 ; 162.35,154.71 J1.15 ; J1.15 163.31,153.75 ; J1.15 164.27,154.71 ; J1.15 163.31,155.67 ; 163.31,179.15 J1.35 ; J1.35 164.27,180.11 ; J1.35 162.35,180.11 ; J1.35 163.31,181.07 ; 163.31,44.53 J3.21 ; J3.21 164.27,45.49 ; J3.21 162.35,45.49 ; J3.21 163.31,46.45 ; 154.35,101.37 J2.19 ; J2.19 155.31,102.33 ; J2.19 155.31,100.41 ; J2.19 156.27,101.37 ; J3.39 163.31,69.31 ; J3.39 164.27,68.35 ; J3.39 163.31,67.39 ; J3.39 162.35,68.35 ; 155.31,95.33 J2.15 ; J2.15 156.27,96.29 ; J2.15 154.35,96.29 ; J2.15 155.31,97.25 ; B1.2 21.68,54.4 ; B1.2 23.88,52.2 ; B1.2 19.48,52.2 ; B1.2 21.68,50 ; 163.31,141.05 J1.5 ; J1.5 162.35,142.01 ; J1.5 164.27,142.01 ; J1.5 163.31,142.97 ; J2.25 156.27,108.99 ; J2.25 154.35,108.99 ; J2.25 155.31,108.03 ; J2.25 155.31,109.95 ; 163.31,168.99 J1.27 ; J1.27 163.31,170.91 ; J1.27 162.35,169.95 ; J1.27 164.27,169.95 ; J2.13 155.31,94.71 ; J2.13 155.31,92.79 ; J2.13 154.35,93.75 ; J2.13 156.27,93.75 ; 155.31,80.09 J2.3 ; J2.3 154.35,81.05 ; J2.3 156.27,81.05 ; J2.3 155.31,82.01 ; J3.25 164.27,50.57 ; J3.25 163.31,49.61 ; J3.25 162.35,50.57 ; J3.25 163.31,51.53 ; J2.17 155.31,99.79 ; J2.17 154.35,98.83 ; J2.17 156.27,98.83 ; J2.17 155.31,97.87 ; J3.13 163.31,36.29 ; J3.13 164.27,35.33 ; J3.13 162.35,35.33 ; J3.13 163.31,34.37 ; J1.11 163.31,150.59 ; J1.11 162.35,149.63 ; J1.11 164.27,149.63 ; J1.11 163.31,148.67 ; 162.35,20.09 J3.1 ; J3.1 164.27,20.09 ; J3.1 163.31,19.13 ; J3.1 163.31,21.05 ; J2.5 156.27,83.59 ; J2.5 154.35,83.59 ; J2.5 155.31,82.63 ; J2.5 155.31,84.55 ; 163.31,24.21 J3.5 ; J3.5 162.35,25.17 ; J3.5 164.27,25.17 ; J3.5 163.31,26.13 ; J2.35 156.27,121.69 ; J2.35 155.31,122.65 ; J2.35 155.31,120.73 ; J2.35 154.35,121.69 ; 163.31,41.99 J3.19 ; J3.19 162.35,42.95 ; J3.19 164.27,42.95 ; J3.19 163.31,43.91 ; J2.39 156.27,126.77 ; J2.39 155.31,127.73 ; J2.39 154.35,126.77 ; J2.39 155.31,125.81 ; J1.31 163.31,175.99 ; J1.31 162.35,175.03 ; J1.31 163.31,174.07 ; J1.31 164.27,175.03 ; J3.31 164.27,58.19 ; J3.31 163.31,57.23 ; J3.31 162.35,58.19 ; J3.31 163.31,59.15 ; J2.1 156.27,78.51 ; J2.1 154.35,78.51 ; J2.1 155.31,77.55 ; J2.1 155.31,79.47 ; 162.35,139.47 J1.3 ; J1.3 163.31,140.43 ; J1.3 164.27,139.47 ; J1.3 163.31,138.51 ; J1.17 163.31,158.21 ; J1.17 162.35,157.25 ; J1.17 164.27,157.25 ; J1.17 163.31,156.29 ; 27.18,112.31 U1.2 ; U1.2 26.08,113.41 ; U1.2 27.18,114.51 ; U1.2 28.28,113.41 ; J2.33 156.27,119.15 ; J2.33 155.31,118.19 ; J2.33 155.31,120.11 ; J2.33 154.35,119.15 ; B1.1 23.88,47.12 ; B1.1 21.68,49.32 ; B1.1 21.68,44.92 ; B1.1 19.48,47.12 ; 162.35,22.63 J3.3 ; J3.3 163.31,21.67 ; J3.3 164.27,22.63 ; J3.3 163.31,23.59
  vias: v2(8.96,192.64) v2(8.96,187.64) v2(8.96,182.64) v2(8.96,177.64) v2(8.96,172.64) v2(8.96,167.64) v2(8.96,162.64) v2(8.96,157.64) v2(8.96,152.64) v2(8.96,147.64) v2(8.96,142.64) v2(8.96,137.64) v2(8.96,132.64) v2(8.96,127.64) v2(8.96,122.64) v2(8.96,117.64) v2(8.96,112.64) v2(8.96,107.64) v2(8.96,102.64) v2(8.96,97.64) v2(8.96,92.64) v2(8.96,87.64) v2(8.96,82.64) v2(8.96,77.64) v2(8.96,72.64) v2(8.96,67.64) v2(8.96,62.64) v2(8.96,57.64) v2(8.96,52.64) v2(8.96,47.64) v2(8.96,42.64) v2(8.96,37.64) v2(8.96,32.64) v2(8.96,27.64) v2(8.96,22.64) v2(8.96,17.64) v2(8.96,12.64) v2(12.46,48.02) v2(12.94,135.91) v2(13.33,123.99) v2(13.42,65.52) v2(13.71,86.1) v2(13.61,35.33) v2(13.9,148.79) v2(14.67,177.64) v2(14.67,103.41) v2(14.86,160.91) v2(16.21,93.99) v2(17.46,195.14) v2(17.46,9.14) v2(17.75,170.91) v2(18.42,76.1) v2(18.9,131.29) v2(19.09,186.49) v2(21.11,15.91) v2(21.88,20.91) v2(23.52,157.26) v2(23.71,148.79) v2(23.9,107.83) v2(24.38,68.79) v2(24.96,85.04) v2(24.96,43.6) v2(25.54,99.76) v2(26.11,176.1) v2(26.02,170.24) v2(26.11,60.33) v2(27.17,165.81) v2(27.36,160.33) v2(27.46,195.14) v2(27.46,9.14) v2(29.67,119.37) v2(29.67,48.79) v2(29.77,145.24) v2(29.77,137.64) v2(29.86,132.64) v2(29.86,43.6) v2(29.86,25.52) v2(30.06,127.26) v2(30.06,33.41) v2(30.15,152.64) v2(30.15,38.51) v2(30.25,182.06) v2(32.46,195.14) v2(32.46,9.14) v2(32.56,70.62) v2(32.65,76.77) v2(32.65,62.93) v2(33.71,85.24) v2(37.46,195.14) v2(37.46,9.14) v2(37.54,20.72) v2(39.75,55.33) v2(39.86,186.68) v2(42.46,195.14) v2(42.46,9.14) v2(42.73,24.08) v2(44.84,177.83) v2(46.77,21.1) v2(47.46,195.14) v2(47.46,9.14) v2(48.74,22.78) v2(49.36,178.22) v2(52.2,20.57) v2(52.46,195.14) v2(52.46,9.14) v2(53.21,182.16) v2(56.58,185.81) v2(57.46,195.14) v2(57.46,9.14) v2(60.71,189.37) v2(61.05,11.15) v2(62.46,195.14) v2(62.46,9.14) v2(66.35,23.1) v2(66.35,20.56) v2(66.44,93.9) v2(66.47,90.03) v2(66.42,86.37) v2(66.42,81.29) v2(66.42,76.13) v2(66.42,73.59) v2(66.42,71.05) v2(66.47,67.34) v2(66.47,64.8) v2(66.47,62.36) v2(66.47,59.82) v2(66.47,57.28) v2(66.47,54.74) v2(66.47,47.12) v2(66.44,33.43) v2(66.54,188.7) v2(66.54,186.16) v2(66.54,183.62) v2(66.54,181.08) v2(66.54,178.54) v2(66.54,176) v2(66.54,168.38) v2(66.54,165.84) v2(66.56,161.09) v2(66.59,152.34) v2(66.59,149.8) v2(66.61,139.15) v2(66.61,136.61) v2(66.61,134.07) v2(66.61,131.53) v2(66.61,128.99) v2(66.56,125.45) v2(66.56,122.91) v2(66.56,117.83) v2(66.56,115.29) v2(66.56,107.67) v2(67.46,195.14) v2(67.46,9.14) v2(67.63,191.68) v2(72.46,195.14) v2(72.46,9.14) v2(76.96,191.2) v2(77.46,195.14) v2(77.46,9.14) v2(80.84,134.08) v2(80.84,131.54) v2(80.84,129) v2(80.86,39.15) v2(80.85,36.62) v2(80.98,163.6) v2(80.98,161.06) v2(80.98,158.52) v2(80.98,155.98) v2(80.94,125.53) v2(80.98,78.38) v2(80.98,75.84) v2(80.98,73.3) v2(80.96,70.38) v2(81.01,67.35) v2(81.01,64.81) v2(81.01,62.27) v2(81.01,59.73) v2(81.04,103.84) v2(81.04,101.3) v2(81.2,18.05) v2(81.2,15.51) v2(81.2,12.97) v2(81.22,188.69) v2(81.22,186.15) v2(81.22,183.61) v2(82.46,195.14) v2(82.46,9.14) v2(87.46,195.14) v2(87.46,9.14) v2(88.31,191.39) v2(92.46,195.14) v2(92.46,9.14) v2(95.86,188.79) v2(95.86,181.17) v2(96,97.55) v2(96,84.87) v2(95.96,25.05) v2(95.96,22.51) v2(96.08,108.96) v2(96.08,106.42) v2(96.08,103.88) v2(96.08,101.34) v2(96.15,39.15) v2(96.15,36.61) v2(96.15,34.07) v2(96.15,31.53) v2(96.27,168.74) v2(96.27,166.2) v2(96.27,163.66) v2(96.27,161.12) v2(96.27,158.58) v2(96.27,156.04) v2(96.27,153.5) v2(96.27,150.96) v2(96.27,145.88) v2(96.29,120.49) v2(96.25,45.72) v2(96.25,43.18) v2(96.37,73.5) v2(96.37,70.96) v2(96.37,13.1) v2(96.49,67.36) v2(96.49,64.82) v2(96.49,59.74) v2(97.46,195.14) v2(97.46,9.14) v2(100.9,191.68) v2(102.46,195.14) v2(105.21,176.3) v2(105.21,173.76) v2(105.21,171.22) v2(105.21,168.68) v2(105.21,166.14) v2(105.21,163.6) v2(105.21,161.06) v2(105.21,158.52) v2(105.21,155.98) v2(105.21,153.44) v2(105.21,150.9) v2(105.21,148.36) v2(105.21,145.82) v2(105.26,64.61) v2(105.51,48.23) v2(105.51,45.69) v2(105.51,43.15) v2(105.47,39.12) v2(105.47,36.58) v2(105.47,34.04) v2(105.47,31.5) v2(105.47,28.96) v2(105.47,26.42) v2(105.79,114.11) v2(105.79,111.57) v2(105.79,109.03) v2(105.79,106.49) v2(105.79,103.95) v2(105.79,101.41) v2(105.76,97.57) v2(105.76,95.03) v2(105.76,92.49) v2(105.76,89.95) v2(107.46,195.14) v2(107.46,9.14) v2(110.9,192.93) v2(112.46,195.14) v2(112.46,9.14) v2(117.46,195.14) v2(117.44,73.99) v2(117.73,13.31) v2(120.1,121.69) v2(120.1,111.53) v2(120.1,106.45) v2(120.1,101.37) v2(120.13,97.57) v2(120.13,95.03) v2(120.13,92.49) v2(120.13,89.95) v2(120.13,87.41) v2(120.13,84.87) v2(120.13,79.79) v2(120.18,58.52) v2(120.16,39.15) v2(120.16,36.61) v2(120.16,34.07) v2(120.16,31.53) v2(120.16,28.99) v2(120.16,26.45) v2(120.16,23.91) v2(120.16,21.37) v2(120.21,48.33) v2(120.21,43.25) v2(120.33,125.32) v2(120.42,176.25) v2(120.42,171.17) v2(120.42,168.63) v2(120.42,166.09) v2(120.42,163.55) v2(120.42,161.01) v2(120.42,158.47) v2(120.42,155.93) v2(120.42,153.39) v2(120.42,150.85) v2(120.42,148.31) v2(120.42,145.77) v2(120.42,143.23) v2(120.42,140.69) v2(120.61,73.41) v2(120.61,16.01) v2(122.06,77.06) v2(122.46,195.14) v2(123.69,189.85) v2(123.69,134.95) v2(124.08,18.6) v2(126.86,186.77) v2(126.86,128.7) v2(127.46,195.14) v2(127.46,9.14) v2(129.27,134.95) v2(129.46,76.49) v2(129.46,18.02) v2(129.7,182.65) v2(129.7,177.57) v2(129.7,172.49) v2(129.7,167.41) v2(129.7,162.33) v2(129.7,157.25) v2(129.7,152.17) v2(129.7,147.09) v2(129.7,142.01) v2(129.7,136.93) v2(129.7,124.23) v2(129.7,119.15) v2(129.7,114.07) v2(129.7,108.99) v2(129.7,103.91) v2(129.7,98.83) v2(129.7,93.75) v2(129.7,88.67) v2(129.7,83.59) v2(129.7,78.51) v2(129.7,65.81) v2(129.7,60.73) v2(129.7,55.65) v2(129.7,50.57) v2(129.7,45.49) v2(129.7,40.41) v2(129.7,35.33) v2(129.7,30.25) v2(129.7,25.17) v2(129.7,20.09) v2(132.34,128.6) v2(132.46,195.14) v2(132.46,9.14) v2(133.11,69.85) v2(133.79,186.97) v2(134.65,134.85) v2(135.61,76.68) v2(135.61,18.12) v2(137.46,195.14) v2(137.46,9.14) v2(139.27,18.31) v2(139.36,135.43) v2(140.81,188.79) v2(141,130.43) v2(141,76.68) v2(141.4,185.19) v2(141.4,180.11) v2(141.4,175.03) v2(141.4,169.95) v2(141.4,164.87) v2(141.4,159.79) v2(141.4,154.71) v2(141.4,149.63) v2(141.4,144.55) v2(141.4,139.47) v2(141.4,126.77) v2(141.4,121.69) v2(141.4,116.61) v2(141.4,111.53) v2(141.4,106.45) v2(141.4,101.37) v2(141.4,96.29) v2(141.4,91.21) v2(141.4,86.13) v2(141.4,81.05) v2(141.4,68.35) v2(141.4,63.27) v2(141.4,58.19) v2(141.4,53.11) v2(141.4,48.03) v2(141.4,42.95) v2(141.4,37.87) v2(141.4,32.79) v2(141.4,27.71) v2(141.4,22.63) v2(141.48,71.68) v2(144.36,135.43) v2(144.56,18.51) v2(146.29,76.68) v2(147.46,195.14) v2(147.46,17.54) v2(147.46,9.14) v2(149.08,128.6) v2(149.56,18.41) v2(149.65,187.16) v2(149.84,70.33) v2(149.94,135.52) v2(153.11,76.2) v2(154.65,134.76) v2(157.54,186.68) v2(164.67,72.16) v2(164.96,128.89) v2(165.06,90.52) v2(165.15,124.47) v2(165.25,119.27) v2(165.25,114.18) v2(165.25,96.49) v2(165.25,84.66) v2(165.25,68.41) v2(165.34,108.41) v2(165.44,180.43) v2(165.44,78.51) v2(165.44,55.62) v2(165.54,64.08) v2(165.54,59.47) v2(165.54,41.2) v2(165.63,103.41) v2(165.63,51.29) v2(165.63,46.49) v2(165.83,175.04) v2(165.83,169.95) v2(165.83,165.62) v2(165.83,148.12) v2(165.83,143.31) v2(165.83,36.01) v2(165.83,31.68) v2(165.83,26.58) v2(165.83,20.72) v2(165.92,161.2) v2(166.02,156.77) v2(166.02,152.35) v2(166.11,138.89) v2(172.96,192.64) v2(172.96,187.64) v2(172.96,182.64) v2(172.96,177.64) v2(172.96,172.64) v2(172.96,167.64) v2(172.96,162.64) v2(172.96,157.64) v2(172.96,152.64) v2(172.96,147.64) v2(172.96,142.64) v2(172.96,137.64) v2(172.96,132.64) v2(172.96,127.64) v2(172.96,122.64) v2(172.96,117.64) v2(172.96,112.64) v2(172.96,107.64) v2(172.96,102.64) v2(172.96,97.64) v2(172.96,92.64) v2(172.96,87.64) v2(172.96,82.64) v2(172.96,77.64) v2(172.96,72.64) v2(172.96,67.64) v2(172.96,62.64) v2(172.96,57.64) v2(172.96,52.64) v2(172.96,47.64) v2(172.96,42.64) v2(172.96,37.64) v2(172.96,32.64) v2(172.96,27.64) v2(172.96,22.64) v2(172.96,17.64) v2(172.96,12.64) v3(12.56,194.39) v3(12.56,9.89) v3(22.56,193.14) v3(22.56,11.14) v3(144.36,193.14) v3(144.36,11.14) v3(154.36,194.39) v3(154.36,9.89)
UNNAMED_1_BORNIER3B_I185_C: length 10
  BOTTOM w1.4: F1.1 B1.3
UNNAMED_1_CAPA_I190_B: length 3
  TOP w1.4: C2.2 S63.2
UNNAMED_1_CAPA_I193_A: length 3.4
  BOTTOM w1: C1.1 15.22,114.35 U1.3
UNNAMED_1_CAPA_I193_B: length 3.4
  BOTTOM w1: C1.2 15.22,117.55 U1.4
UNNAMED_1_CON40P_I1_A: length 26
  BOTTOM w0.6: v1(148.96,147.09) J1.10
  BOTTOM w0.8: R16.1 v1(148.96,147.09)
UNNAMED_1_CON40P_I1_A_1: length 14.3
  BOTTOM w0.6: v1(148.96,144.55) J1.8
  BOTTOM w0.8: R17.1 v1(148.96,144.55)
UNNAMED_1_CON40P_I1_A_2: length 26
  BOTTOM w0.6: v1(148.96,142.01) J1.6
  BOTTOM w0.8: v1(148.96,142.01) R18.1
UNNAMED_1_CON40P_I1_A_3: length 14.3
  BOTTOM w0.6: v1(148.96,139.47) J1.4
  BOTTOM w0.8: R19.1 v1(148.96,139.47)
UNNAMED_1_CON40P_I1_A_4: length 14.3
  BOTTOM w0.6: R1.1 v1(148.96,185.19) J1.40
UNNAMED_1_CON40P_I1_A_5: length 26
  BOTTOM w0.6: v1(148.96,182.65) J1.38
  BOTTOM w0.8: v1(148.96,182.65) R2.1
UNNAMED_1_CON40P_I1_A_6: length 14.3
  BOTTOM w0.6: v1(148.96,180.11) J1.36
  BOTTOM w0.8: R3.1 v1(148.96,180.11)
UNNAMED_1_CON40P_I1_A_7: length 26
  BOTTOM w0.6: v1(148.96,177.57) J1.34
  BOTTOM w0.8: R4.1 v1(148.96,177.57)
UNNAMED_1_CON40P_I1_A_8: length 14.3
  BOTTOM w0.6: v1(148.96,175.03) J1.32
  BOTTOM w0.8: R5.1 v1(148.96,175.03)
UNNAMED_1_CON40P_I1_A_9: length 26
  BOTTOM w0.6: v1(148.96,172.49) J1.30
  BOTTOM w0.8: R6.1 v1(148.96,172.49)
UNNAMED_1_CON40P_I1_A_10: length 14.3
  BOTTOM w0.6: v1(148.96,169.95) J1.28
  BOTTOM w0.8: R7.1 v1(148.96,169.95)
UNNAMED_1_CON40P_I1_A_11: length 26
  BOTTOM w0.6: v1(148.96,167.41) J1.26
  BOTTOM w0.8: R8.1 v1(148.96,167.41)
UNNAMED_1_CON40P_I1_A_12: length 14.3
  BOTTOM w0.6: v1(148.96,164.87) J1.24
  BOTTOM w0.8: R9.1 v1(148.96,164.87)
UNNAMED_1_CON40P_I1_A_13: length 26
  BOTTOM w0.6: v1(148.96,162.33) J1.22
  BOTTOM w0.8: R10.1 v1(148.96,162.33)
UNNAMED_1_CON40P_I1_A_14: length 26
  BOTTOM w0.6: v1(148.96,136.93) J1.2
  BOTTOM w0.8: v1(148.96,136.93) R20.1
UNNAMED_1_CON40P_I1_A_15: length 14.3
  BOTTOM w0.6: v1(148.96,159.79) J1.20
  BOTTOM w0.8: R11.1 v1(148.96,159.79)
UNNAMED_1_CON40P_I1_A_16: length 26
  BOTTOM w0.6: v1(148.96,157.25) J1.18
  BOTTOM w0.8: R12.1 v1(148.96,157.25)
UNNAMED_1_CON40P_I1_A_17: length 14.3
  BOTTOM w0.6: v1(148.96,154.71) J1.16
  BOTTOM w0.8: R13.1 v1(148.96,154.71)
UNNAMED_1_CON40P_I1_A_18: length 26
  BOTTOM w0.6: v1(148.96,152.17) J1.14
  BOTTOM w0.8: R14.1 v1(148.96,152.17)
UNNAMED_1_CON40P_I1_A_19: length 14.3
  BOTTOM w0.6: v1(148.96,149.63) J1.12
  BOTTOM w0.8: R15.1 v1(148.96,149.63)
UNNAMED_1_CON40P_I2_A: length 14.3
  BOTTOM w0.6: v1(148.96,53.11) J3.28
  BOTTOM w0.8: R47.1 v1(148.96,53.11)
UNNAMED_1_CON40P_I2_A_1: length 26
  BOTTOM w0.6: v1(148.96,55.65) J3.30
  BOTTOM w0.8: R46.1 v1(148.96,55.65)
UNNAMED_1_CON40P_I2_A_2: length 26
  BOTTOM w0.6: v1(148.96,65.81) J3.38
  BOTTOM w0.8: R42.1 v1(148.96,65.81)
UNNAMED_1_CON40P_I2_A_3: length 14.3
  BOTTOM w0.6: v1(148.96,58.19) J3.32
  BOTTOM w0.8: R45.1 v1(148.96,58.19)
UNNAMED_1_CON40P_I2_A_4: length 26
  BOTTOM w0.6: v1(148.96,60.73) J3.34
  BOTTOM w0.8: R44.1 v1(148.96,60.73)
UNNAMED_1_CON40P_I2_A_5: length 14.3
  BOTTOM w0.6: v1(148.96,63.27) J3.36
  BOTTOM w0.8: R43.1 v1(148.96,63.27)
UNNAMED_1_CON40P_I2_A_6: length 14.3
  BOTTOM w0.6: v1(148.96,68.35) J3.40
  BOTTOM w0.8: R41.1 v1(148.96,68.35)
UNNAMED_1_CON40P_I2_A_7: length 26
  BOTTOM w0.6: v1(148.96,25.17) J3.6
  BOTTOM w0.8: R58.1 v1(148.96,25.17)
UNNAMED_1_CON40P_I2_A_8: length 14.3
  BOTTOM w0.6: v1(148.96,27.71) J3.8
  BOTTOM w0.8: R57.1 v1(148.96,27.71)
UNNAMED_1_CON40P_I2_A_9: length 14.3
  BOTTOM w0.6: v1(148.96,22.63) J3.4
  BOTTOM w0.8: R59.1 v1(148.96,22.63)
UNNAMED_1_CON40P_I2_A_10: length 26
  BOTTOM w0.6: R60.1 J3.2
UNNAMED_1_CON40P_I2_A_11: length 26
  BOTTOM w0.6: v1(148.96,30.25) J3.10
  BOTTOM w0.8: R56.1 v1(148.96,30.25)
UNNAMED_1_CON40P_I2_A_12: length 14.3
  BOTTOM w0.6: v1(148.96,32.79) J3.12
  BOTTOM w0.8: R55.1 v1(148.96,32.79)
UNNAMED_1_CON40P_I2_A_13: length 26
  BOTTOM w0.6: v1(148.96,35.33) J3.14
  BOTTOM w0.8: R54.1 v1(148.96,35.33)
UNNAMED_1_CON40P_I2_A_14: length 14.3
  BOTTOM w0.6: v1(148.96,37.87) J3.16
  BOTTOM w0.8: R53.1 v1(148.96,37.87)
UNNAMED_1_CON40P_I2_A_15: length 26
  BOTTOM w0.6: v1(148.96,40.41) J3.18
  BOTTOM w0.8: R52.1 v1(148.96,40.41)
UNNAMED_1_CON40P_I2_A_16: length 14.3
  BOTTOM w0.6: v1(148.96,42.95) J3.20
  BOTTOM w0.8: R51.1 v1(148.96,42.95)
UNNAMED_1_CON40P_I2_A_17: length 26
  BOTTOM w0.6: v1(148.96,45.49) J3.22
  BOTTOM w0.8: R50.1 v1(148.96,45.49)
UNNAMED_1_CON40P_I2_A_18: length 14.3
  BOTTOM w0.6: v1(148.96,48.03) J3.24
  BOTTOM w0.8: R49.1 v1(148.96,48.03)
UNNAMED_1_CON40P_I2_A_19: length 26
  BOTTOM w0.6: v1(148.96,50.57) J3.26
  BOTTOM w0.8: R48.1 v1(148.96,50.57)
UNNAMED_1_CON40P_I3_A: length 6.3
  BOTTOM w0.6: v1(148.96,111.53) J2.28
  BOTTOM w0.8: R27.1 v1(148.96,111.53)
UNNAMED_1_CON40P_I3_A_1: length 18
  BOTTOM w0.6: v1(148.96,114.07) J2.30
  BOTTOM w0.8: R26.1 v1(148.96,114.07)
UNNAMED_1_CON40P_I3_A_2: length 18
  BOTTOM w0.6: v1(148.96,124.23) J2.38
  BOTTOM w0.8: R22.1 v1(148.96,124.23)
UNNAMED_1_CON40P_I3_A_3: length 6.3
  BOTTOM w0.6: v1(148.96,116.61) J2.32
  BOTTOM w0.8: R25.1 v1(148.96,116.61)
UNNAMED_1_CON40P_I3_A_4: length 18
  BOTTOM w0.6: v1(148.96,119.15) J2.34
  BOTTOM w0.8: R24.1 v1(148.96,119.15)
UNNAMED_1_CON40P_I3_A_5: length 6.3
  BOTTOM w0.6: v1(148.96,121.69) J2.36
  BOTTOM w0.8: R23.1 v1(148.96,121.69)
UNNAMED_1_CON40P_I3_A_6: length 6.3
  BOTTOM w0.6: v1(148.96,126.77) J2.40
  BOTTOM w0.8: R21.1 v1(148.96,126.77)
UNNAMED_1_CON40P_I3_A_7: length 18
  BOTTOM w0.6: v1(148.96,83.59) J2.6
  BOTTOM w0.8: R38.1 v1(148.96,83.59)
UNNAMED_1_CON40P_I3_A_8: length 6.3
  BOTTOM w0.6: v1(148.96,86.13) J2.8
  BOTTOM w0.8: R37.1 v1(148.96,86.13)
UNNAMED_1_CON40P_I3_A_9: length 6.3
  BOTTOM w0.6: v1(148.96,81.05) J2.4
  BOTTOM w0.8: R39.1 v1(148.96,81.05)
UNNAMED_1_CON40P_I3_A_10: length 18
  BOTTOM w0.6: v1(148.96,78.51) J2.2
  BOTTOM w0.8: R40.1 v1(148.96,78.51)
UNNAMED_1_CON40P_I3_A_11: length 18
  BOTTOM w0.6: v1(148.96,88.67) J2.10
  BOTTOM w0.8: R36.1 v1(148.96,88.67)
UNNAMED_1_CON40P_I3_A_12: length 6.3
  BOTTOM w0.6: v1(148.96,91.21) J2.12
  BOTTOM w0.8: R35.1 v1(148.96,91.21)
UNNAMED_1_CON40P_I3_A_13: length 18
  BOTTOM w0.6: v1(148.96,93.75) J2.14
  BOTTOM w0.8: R34.1 v1(148.96,93.75)
UNNAMED_1_CON40P_I3_A_14: length 6.3
  BOTTOM w0.6: v1(148.96,96.29) J2.16
  BOTTOM w0.8: v1(148.96,96.29) R33.1
UNNAMED_1_CON40P_I3_A_15: length 18
  BOTTOM w0.6: v1(148.96,98.83) J2.18
  BOTTOM w0.8: R32.1 v1(148.96,98.83)
UNNAMED_1_CON40P_I3_A_16: length 6.3
  BOTTOM w0.6: v1(148.96,101.37) J2.20
  BOTTOM w0.8: R31.1 v1(148.96,101.37)
UNNAMED_1_CON40P_I3_A_17: length 18
  BOTTOM w0.6: v1(148.96,103.91) J2.22
  BOTTOM w0.8: R30.1 v1(148.96,103.91)
UNNAMED_1_CON40P_I3_A_18: length 6.3
  BOTTOM w0.6: v1(148.96,106.45) J2.24
  BOTTOM w0.8: R29.1 v1(148.96,106.45)
UNNAMED_1_CON40P_I3_A_19: length 18
  BOTTOM w0.6: v1(148.96,108.99) J2.26
  BOTTOM w0.8: R28.1 v1(148.96,108.99)
UNNAMED_1_CONVACDCTUHS10_I194_A: length 7
  BOTTOM w1.4: U1.1 S61.2
UNNAMED_1_FUSUP2P_I186_B: length 23.7
  BOTTOM w1.4: S63.1 25.56,93.66 F1.2 S62.1 21.68,101.21 20.68,102.21 S61.1
UNNAMED_1_POT_I5_A: length 75.8
  BOTTOM w0.6: S1.1 63.68,190 PO1.1
UNNAMED_1_POT_I5_B: length 15.5
  BOTTOM w0.8: PO1.2 124.06,185.19 R1.2
UNNAMED_1_POT_I7_A: length 69.4
  BOTTOM w0.6: S2.1 63.68,187.46 PO2.1
UNNAMED_1_POT_I7_B: length 10.1
  BOTTOM w0.8: R2.2 117.71,182.65 PO2.2
UNNAMED_1_POT_I26_A: length 63.1
  BOTTOM w0.6: S3.1 63.68,184.92 PO3.1
UNNAMED_1_POT_I26_B: length 28.2
  BOTTOM w0.8: R3.2 111.36,180.11 PO3.2
UNNAMED_1_POT_I27_A: length 57
  BOTTOM w0.6: S4.1 49.4,168.66 63.13,182.38 PO4.1
UNNAMED_1_POT_I27_B: length 22.8
  BOTTOM w0.8: PO4.2 105.01,177.57 R4.2
UNNAMED_1_POT_I28_A: length 51.5
  BOTTOM w0.6: S5.1 50.7,166.86 50.7,168.84 61.7,179.84 PO5.1
UNNAMED_1_POT_I28_B: length 40.9
  BOTTOM w0.8: PO5.2 98.66,175.03 R5.2
UNNAMED_1_POT_I29_A: length 45.8
  BOTTOM w0.6: PO6.1 60.67,177.3 51.52,168.15 51.52,165.14 S6.1
UNNAMED_1_POT_I29_B: length 35.5
  BOTTOM w0.8: R6.2 92.31,172.49 PO6.2
UNNAMED_1_POT_I30_A: length 40.1
  BOTTOM w0.6: PO7.1 59.44,174.76 52.27,167.59 52.27,163.35 S7.1
UNNAMED_1_POT_I30_B: length 53.6
  BOTTOM w0.8: PO7.2 85.96,169.95 R7.2
UNNAMED_1_POT_I31_A: length 34.5
  BOTTOM w0.6: S8.1 53,161.54 53,167.01 58.21,172.22 PO8.1
UNNAMED_1_POT_I31_B: length 48.2
  BOTTOM w0.8: R8.2 79.61,167.41 PO8.2
UNNAMED_1_POT_I32_A: length 28.9
  BOTTOM w0.6: S9.1 53.73,159.72 53.73,166.39 57.01,169.68 PO9.1
UNNAMED_1_POT_I32_B: length 66.3
  BOTTOM w0.8: R9.2 73.26,164.87 PO9.2
UNNAMED_1_POT_I33_A: length 23.2
  BOTTOM w0.6: PO10.1 55.92,167.14 54.45,165.67 54.45,157.91 S10.1
UNNAMED_1_POT_I33_B: length 60.9
  BOTTOM w0.8: PO10.2 66.91,162.33 R10.2
UNNAMED_1_POT_I34_A: length 18.1
  BOTTOM w0.6: PO11.1 55.75,161.87 57.19,160.43 57.19,158.11 S11.1
UNNAMED_1_POT_I34_B: length 79
  BOTTOM w0.8: R11.2 60.56,159.79 PO11.2
UNNAMED_1_POT_I35_A: length 16.5
  BOTTOM w0.6: PO12.1 58.69,157.07 S12.1
UNNAMED_1_POT_I35_B: length 61.1
  BOTTOM w0.8: R12.2 67.36,157.25 PO12.2
UNNAMED_1_POT_I36_A: length 22.9
  BOTTOM w0.6: PO13.1 66.92,154.53 63.2,150.81 54.97,150.81 S13.1
UNNAMED_1_POT_I36_B: length 66.4
  BOTTOM w0.8: PO13.2 73.71,154.71 R13.2
UNNAMED_1_POT_I37_A: length 29.2
  BOTTOM w0.6: PO14.1 73.18,151.99 69.21,148.02 54.72,148.02 S14.1
UNNAMED_1_POT_I37_B: length 48.4
  BOTTOM w0.8: R14.2 80.06,152.17 PO14.2
UNNAMED_1_POT_I38_A: length 35.6
  BOTTOM w0.6: S15.1 54.67,145.43 75.51,145.43 79.53,149.45 PO15.1
UNNAMED_1_POT_I38_B: length 53.7
  BOTTOM w0.8: R15.2 86.41,149.63 PO15.2
UNNAMED_1_POT_I39_A: length 41.9
  BOTTOM w0.6: PO16.1 83.71,143.12 54.9,143.12 S16.1
UNNAMED_1_POT_I39_B: length 35.7
  BOTTOM w0.8: R16.2 92.76,147.09 PO16.2
UNNAMED_1_POT_I40_A: length 48.3
  BOTTOM w0.6: S17.1 54.8,140.48 89.96,140.48 PO17.1
UNNAMED_1_POT_I40_B: length 41
  BOTTOM w0.8: R17.2 99.11,144.55 PO17.2
UNNAMED_1_POT_I41_A: length 54.6
  BOTTOM w0.6: S18.1 54.95,138.09 96.46,138.09 PO18.1
UNNAMED_1_POT_I41_B: length 23
  BOTTOM w0.8: PO18.2 105.46,142.01 R18.2
UNNAMED_1_POT_I42_A: length 61
  BOTTOM w0.6: S19.1 54.85,135.45 102.71,135.45 PO19.1
UNNAMED_1_POT_I42_B: length 28.3
  BOTTOM w0.8: PO19.2 111.81,139.47 R19.2
UNNAMED_1_POT_I43_A: length 67.3
  BOTTOM w0.6: S20.1 54.65,132.71 108.86,132.71 PO20.1
UNNAMED_1_POT_I43_B: length 10.3
  BOTTOM w0.8: PO20.2 118.16,136.93 R20.2
UNNAMED_1_POT_I44_A: length 66.8
  BOTTOM w0.6: PO40.1 109.2,72.45 53.61,72.45 S40.1
UNNAMED_1_POT_I44_B: length 11.2
  BOTTOM w0.8: R40.2 120.34,78.51 PO40.2
UNNAMED_1_POT_I45_A: length 60.5
  BOTTOM w0.6: PO39.1 102.75,74.89 53.7,74.89 S39.1
UNNAMED_1_POT_I45_B: length 29.2
  BOTTOM w0.8: PO39.2 113.99,81.05 R39.2
UNNAMED_1_POT_I46_A: length 54.2
  BOTTOM w0.6: S38.1 53.75,77.38 96.35,77.38 PO38.1
UNNAMED_1_POT_I46_B: length 23.9
  BOTTOM w0.8: PO38.2 107.64,83.59 R38.2
UNNAMED_1_POT_I47_A: length 20.7
  BOTTOM w0.6: S33.1 50.61,94.44 50.67,94.5 61.15,94.5 63.41,92.24 66.76,92.24 PO33.1
UNNAMED_1_POT_I47_B: length 67.3
  BOTTOM w0.8: PO33.2 75.89,96.29 R33.2
UNNAMED_1_POT_I48_A: length 12.9
  BOTTOM w0.6: PO32.1 51.12,96.47 50.61,96.98 S32.1
UNNAMED_1_POT_I48_B: length 62
  BOTTOM w0.8: R32.2 69.54,98.83 PO32.2
UNNAMED_1_POT_I49_A: length 8.2
  BOTTOM w0.6: S31.1 53.79,103.91 PO31.1
UNNAMED_1_POT_I49_B: length 79.1
  BOTTOM w0.8: PO31.2 59.56,102.64 133.54,102.64 134.8,101.37 R31.2
UNNAMED_1_POT_I50_A: length 14.5
  BOTTOM w0.6: S30.1 53.79,106.45 PO30.1
UNNAMED_1_POT_I50_B: length 61
  BOTTOM w0.8: R30.2 123.34,105.18 65.91,105.18 PO30.2
UNNAMED_1_POT_I51_A: length 20.9
  BOTTOM w0.6: S29.1 53.79,108.99 PO29.1
UNNAMED_1_POT_I51_B: length 66.4
  BOTTOM w0.8: PO29.2 72.26,107.72 133.54,107.72 134.8,106.45 R29.2
UNNAMED_1_POT_I52_A: length 33.6
  BOTTOM w0.6: PO27.1 53.79,114.07 S27.1
UNNAMED_1_POT_I52_B: length 53.7
  BOTTOM w0.8: PO27.2 84.96,112.8 133.54,112.8 134.8,111.53 R27.2
UNNAMED_1_POT_I53_A: length 27.2
  BOTTOM w0.6: S28.1 53.79,111.53 PO28.1
